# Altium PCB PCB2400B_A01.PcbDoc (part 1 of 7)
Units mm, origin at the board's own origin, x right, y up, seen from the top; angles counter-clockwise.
Board outline 115 x 60 mm, 6 copper layers (Top Layer, Signal Layer 2, Signal Layer 3, Signal Layer 4, Signal Layer 5, Bottom Layer), stack 1.555 mm thick; 382 components, 308 nets, 1384 pads, 1152 vias.
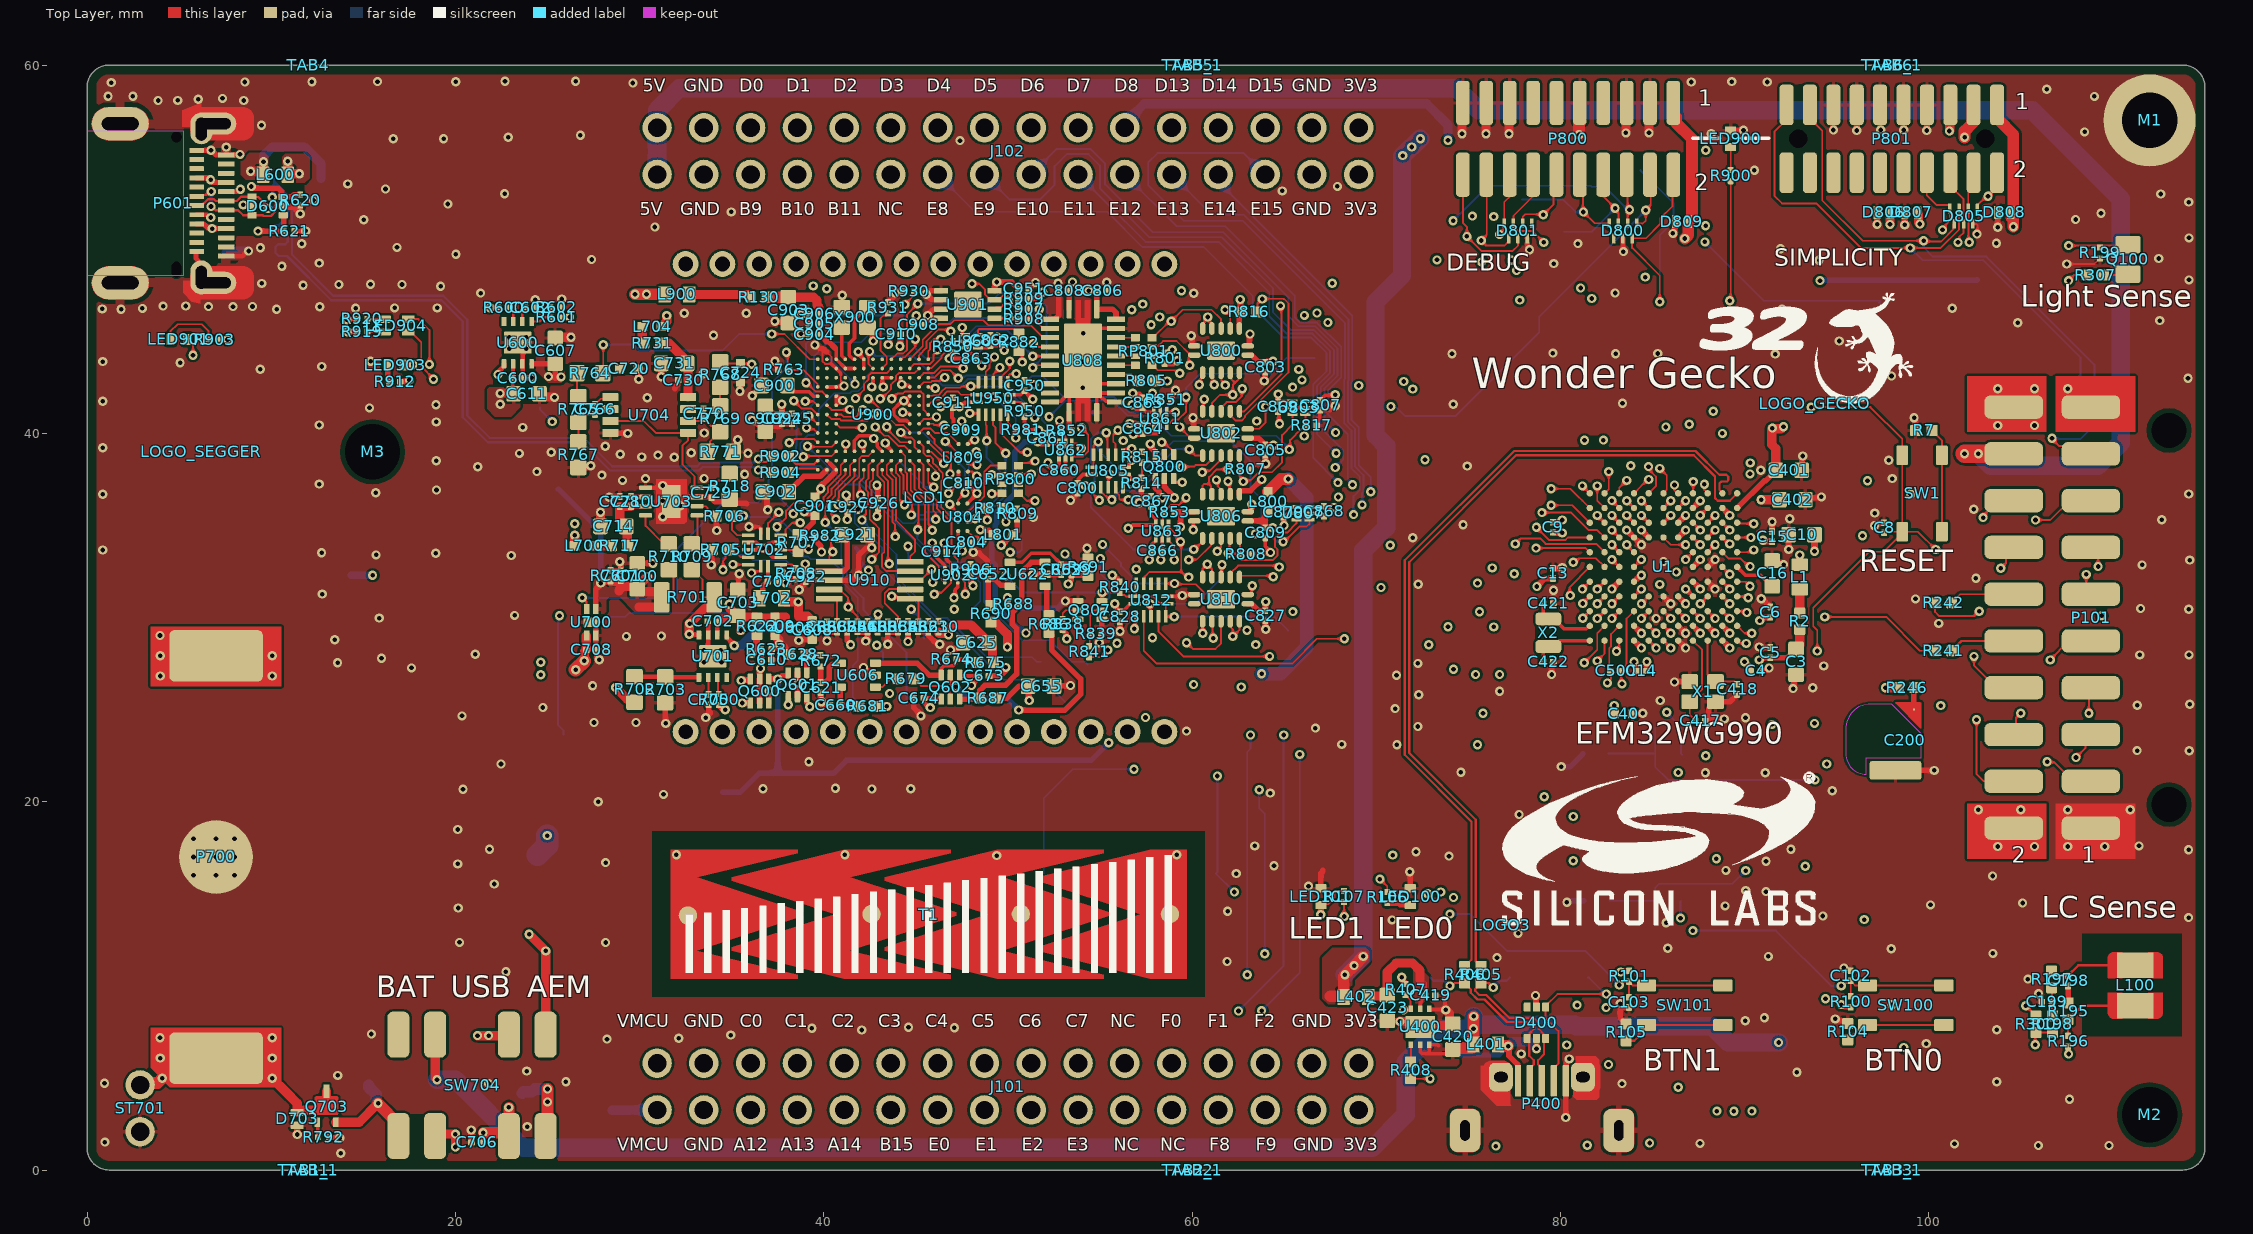
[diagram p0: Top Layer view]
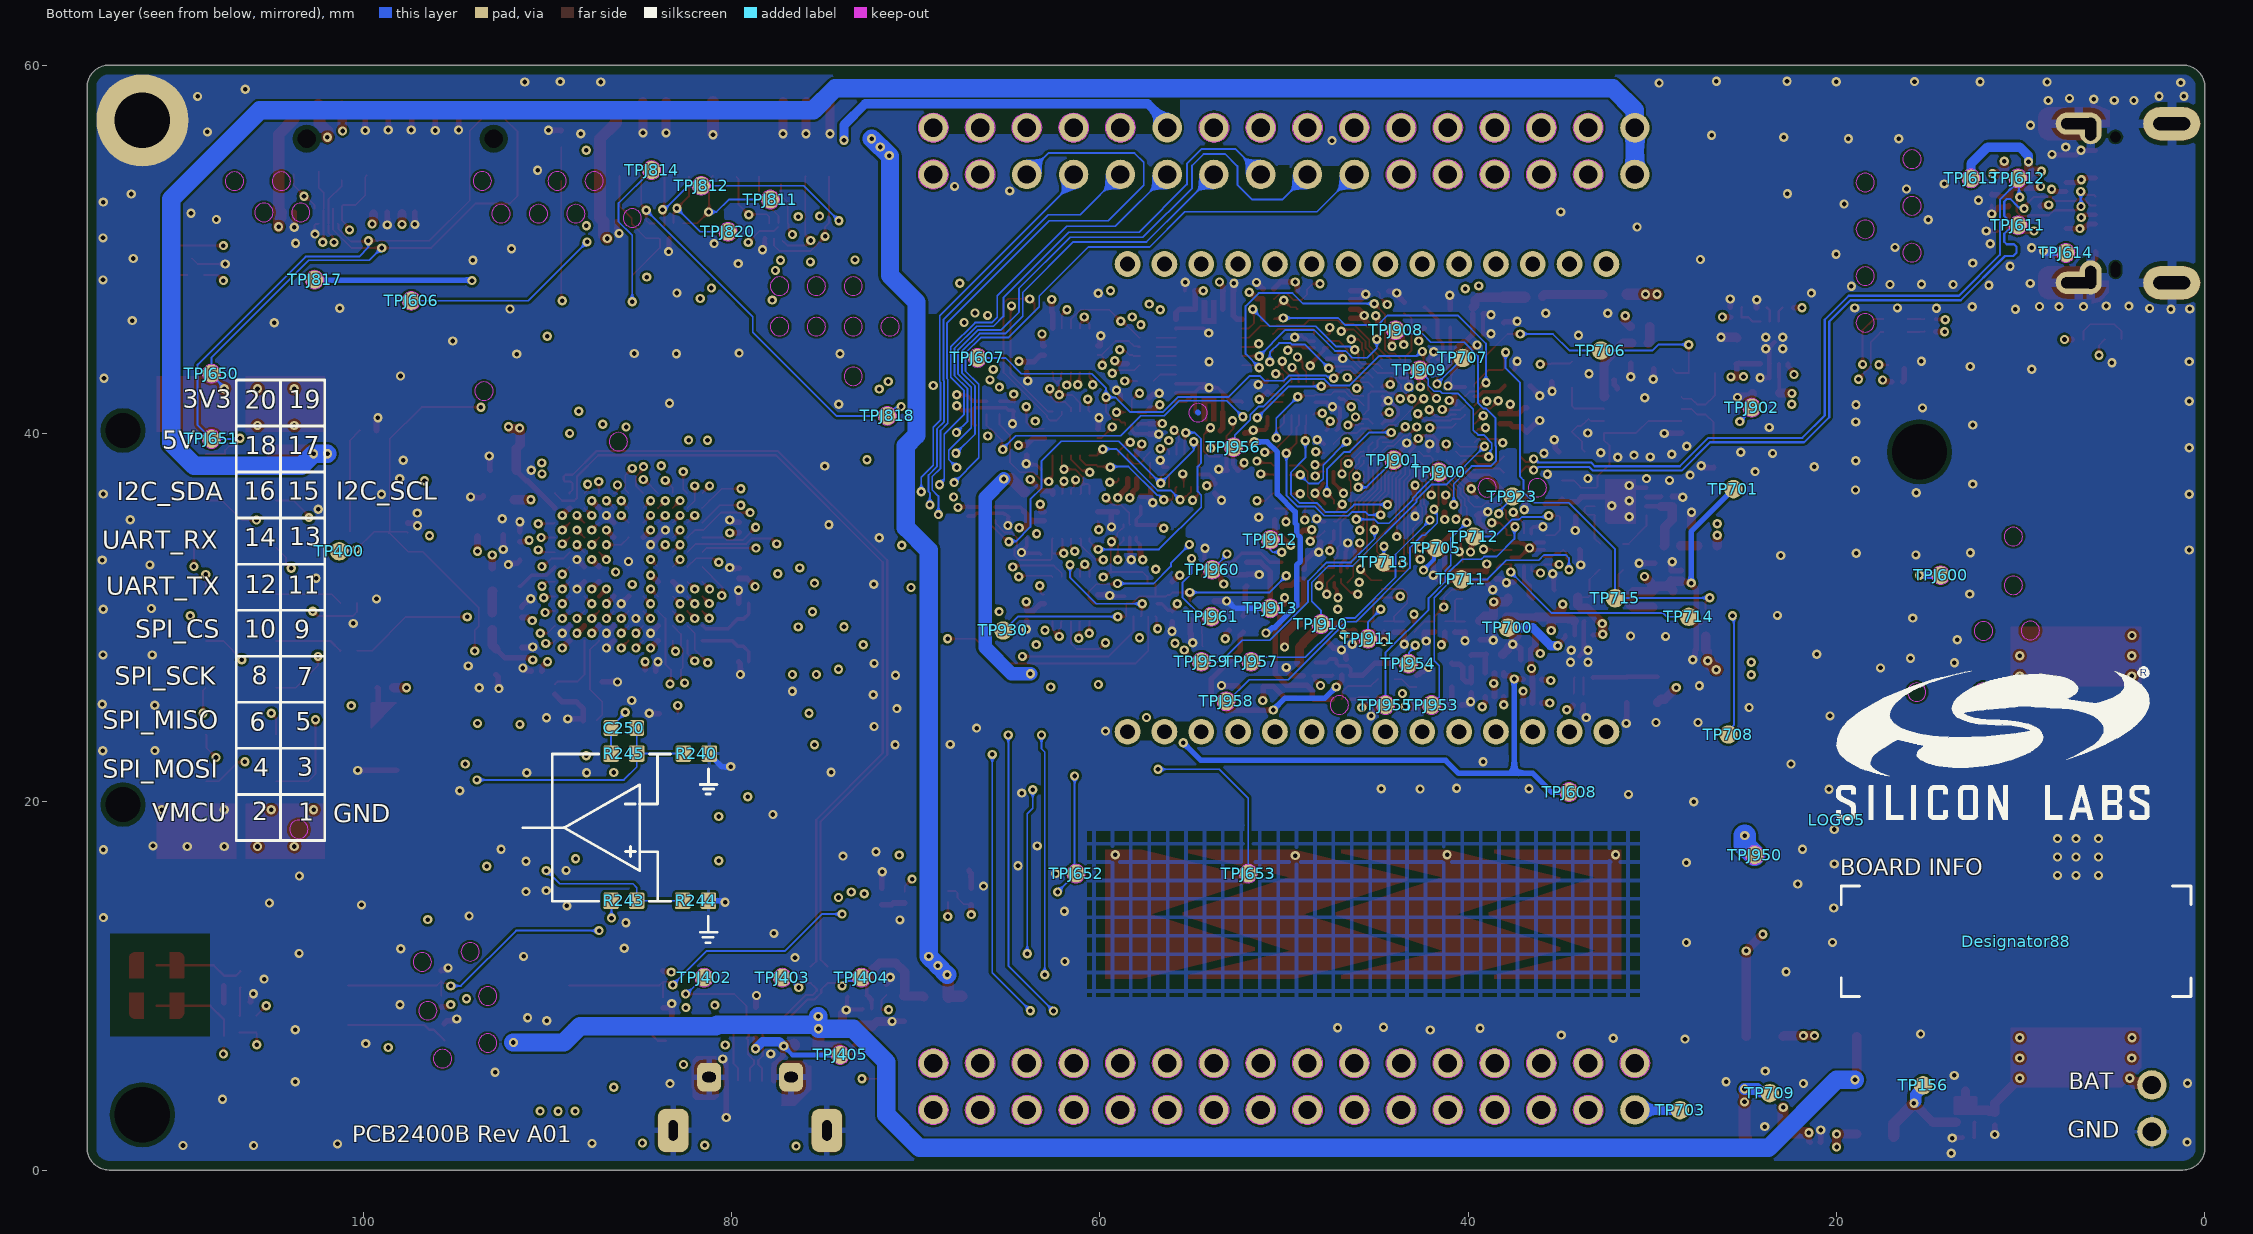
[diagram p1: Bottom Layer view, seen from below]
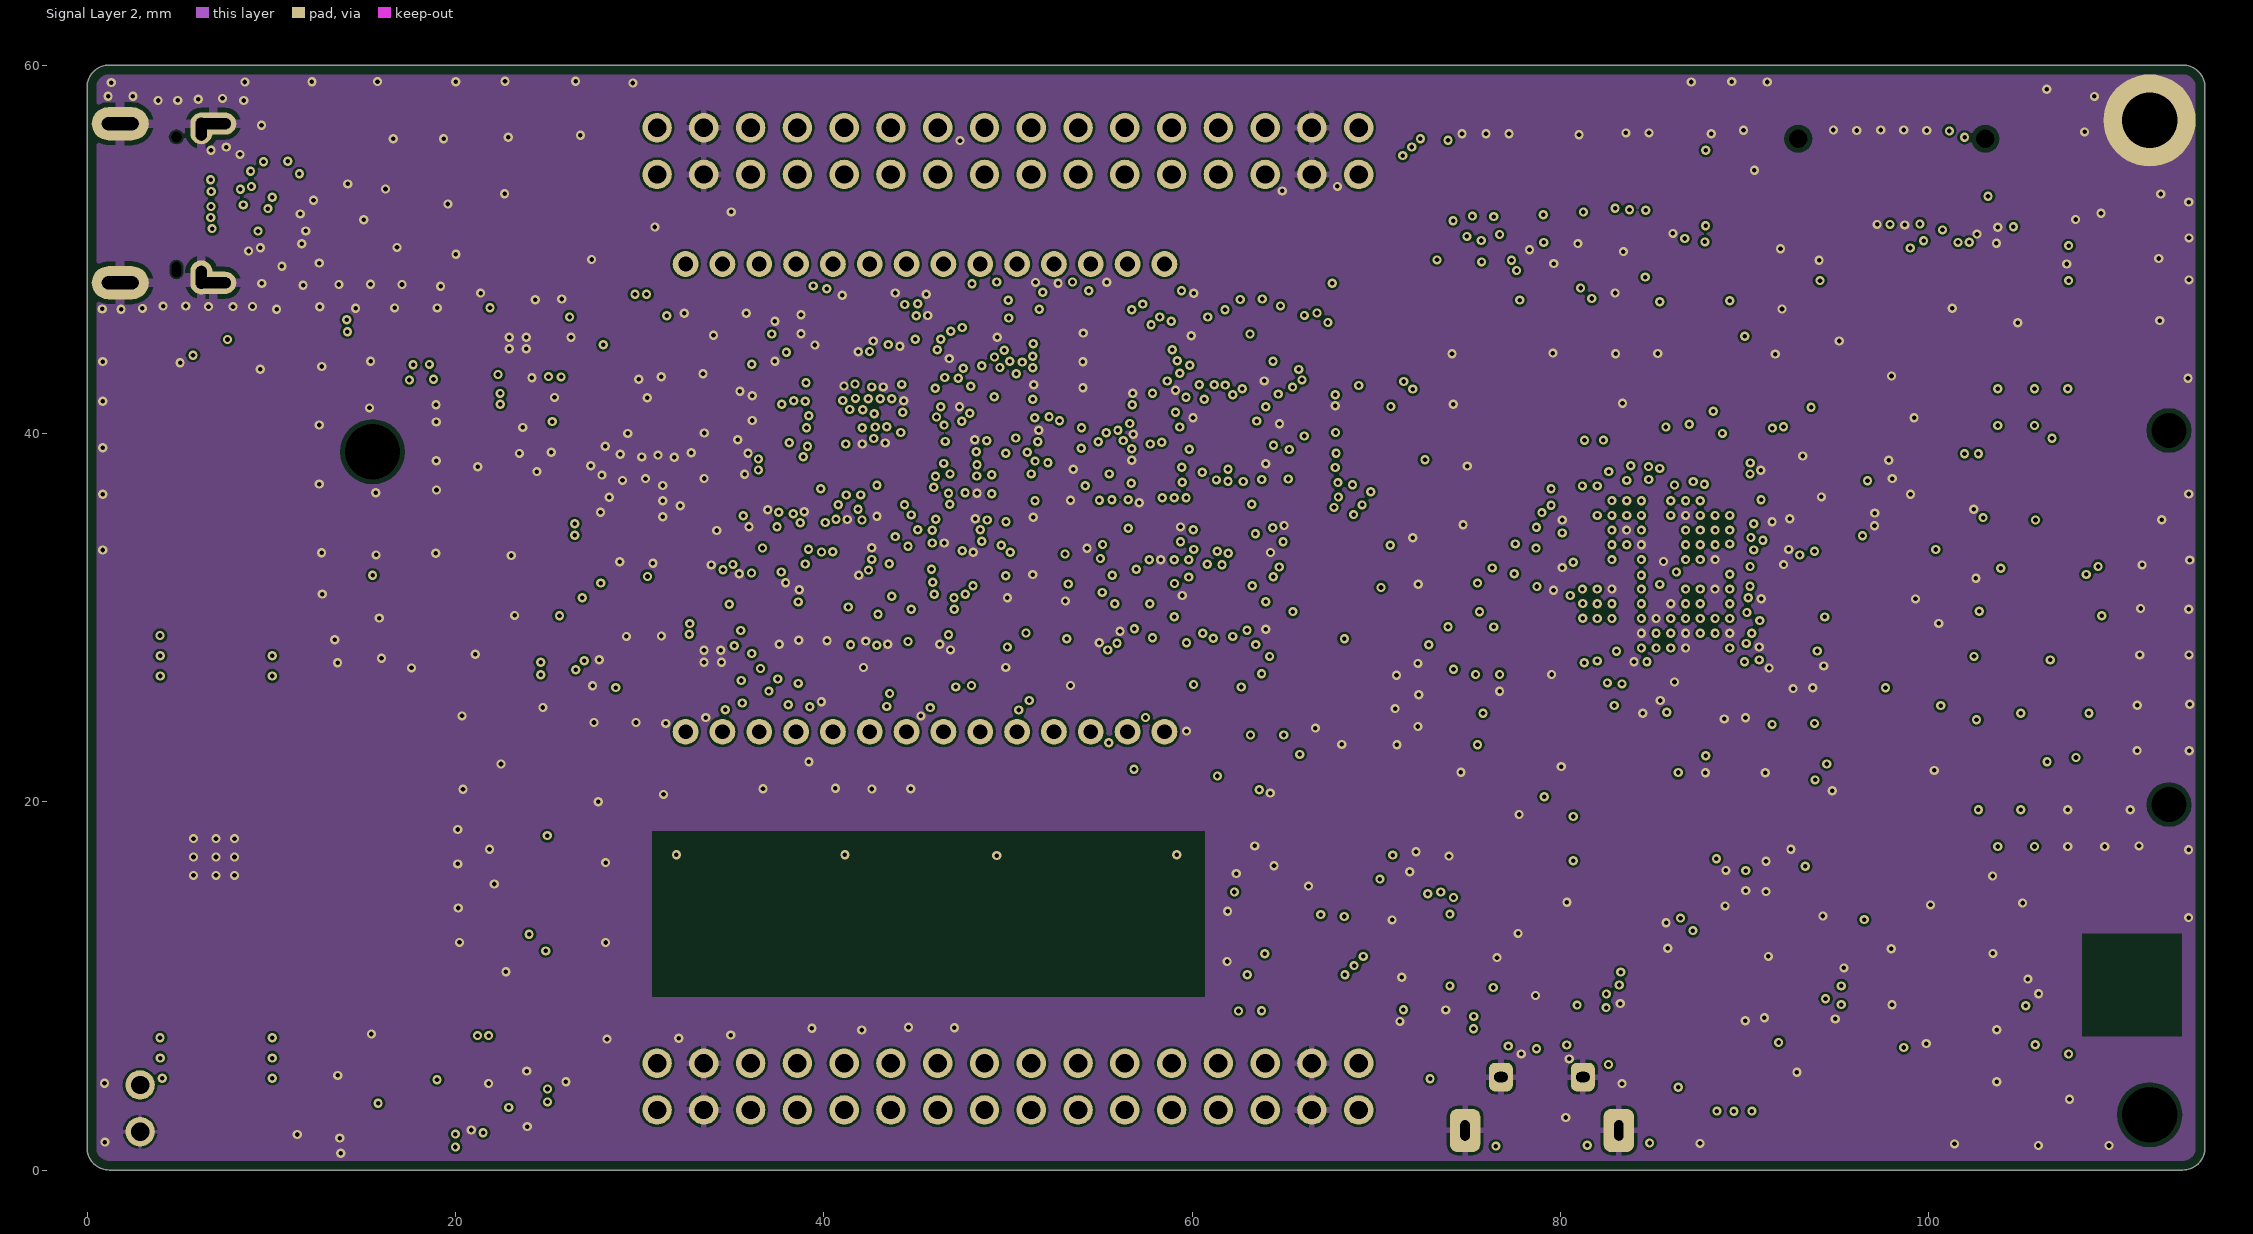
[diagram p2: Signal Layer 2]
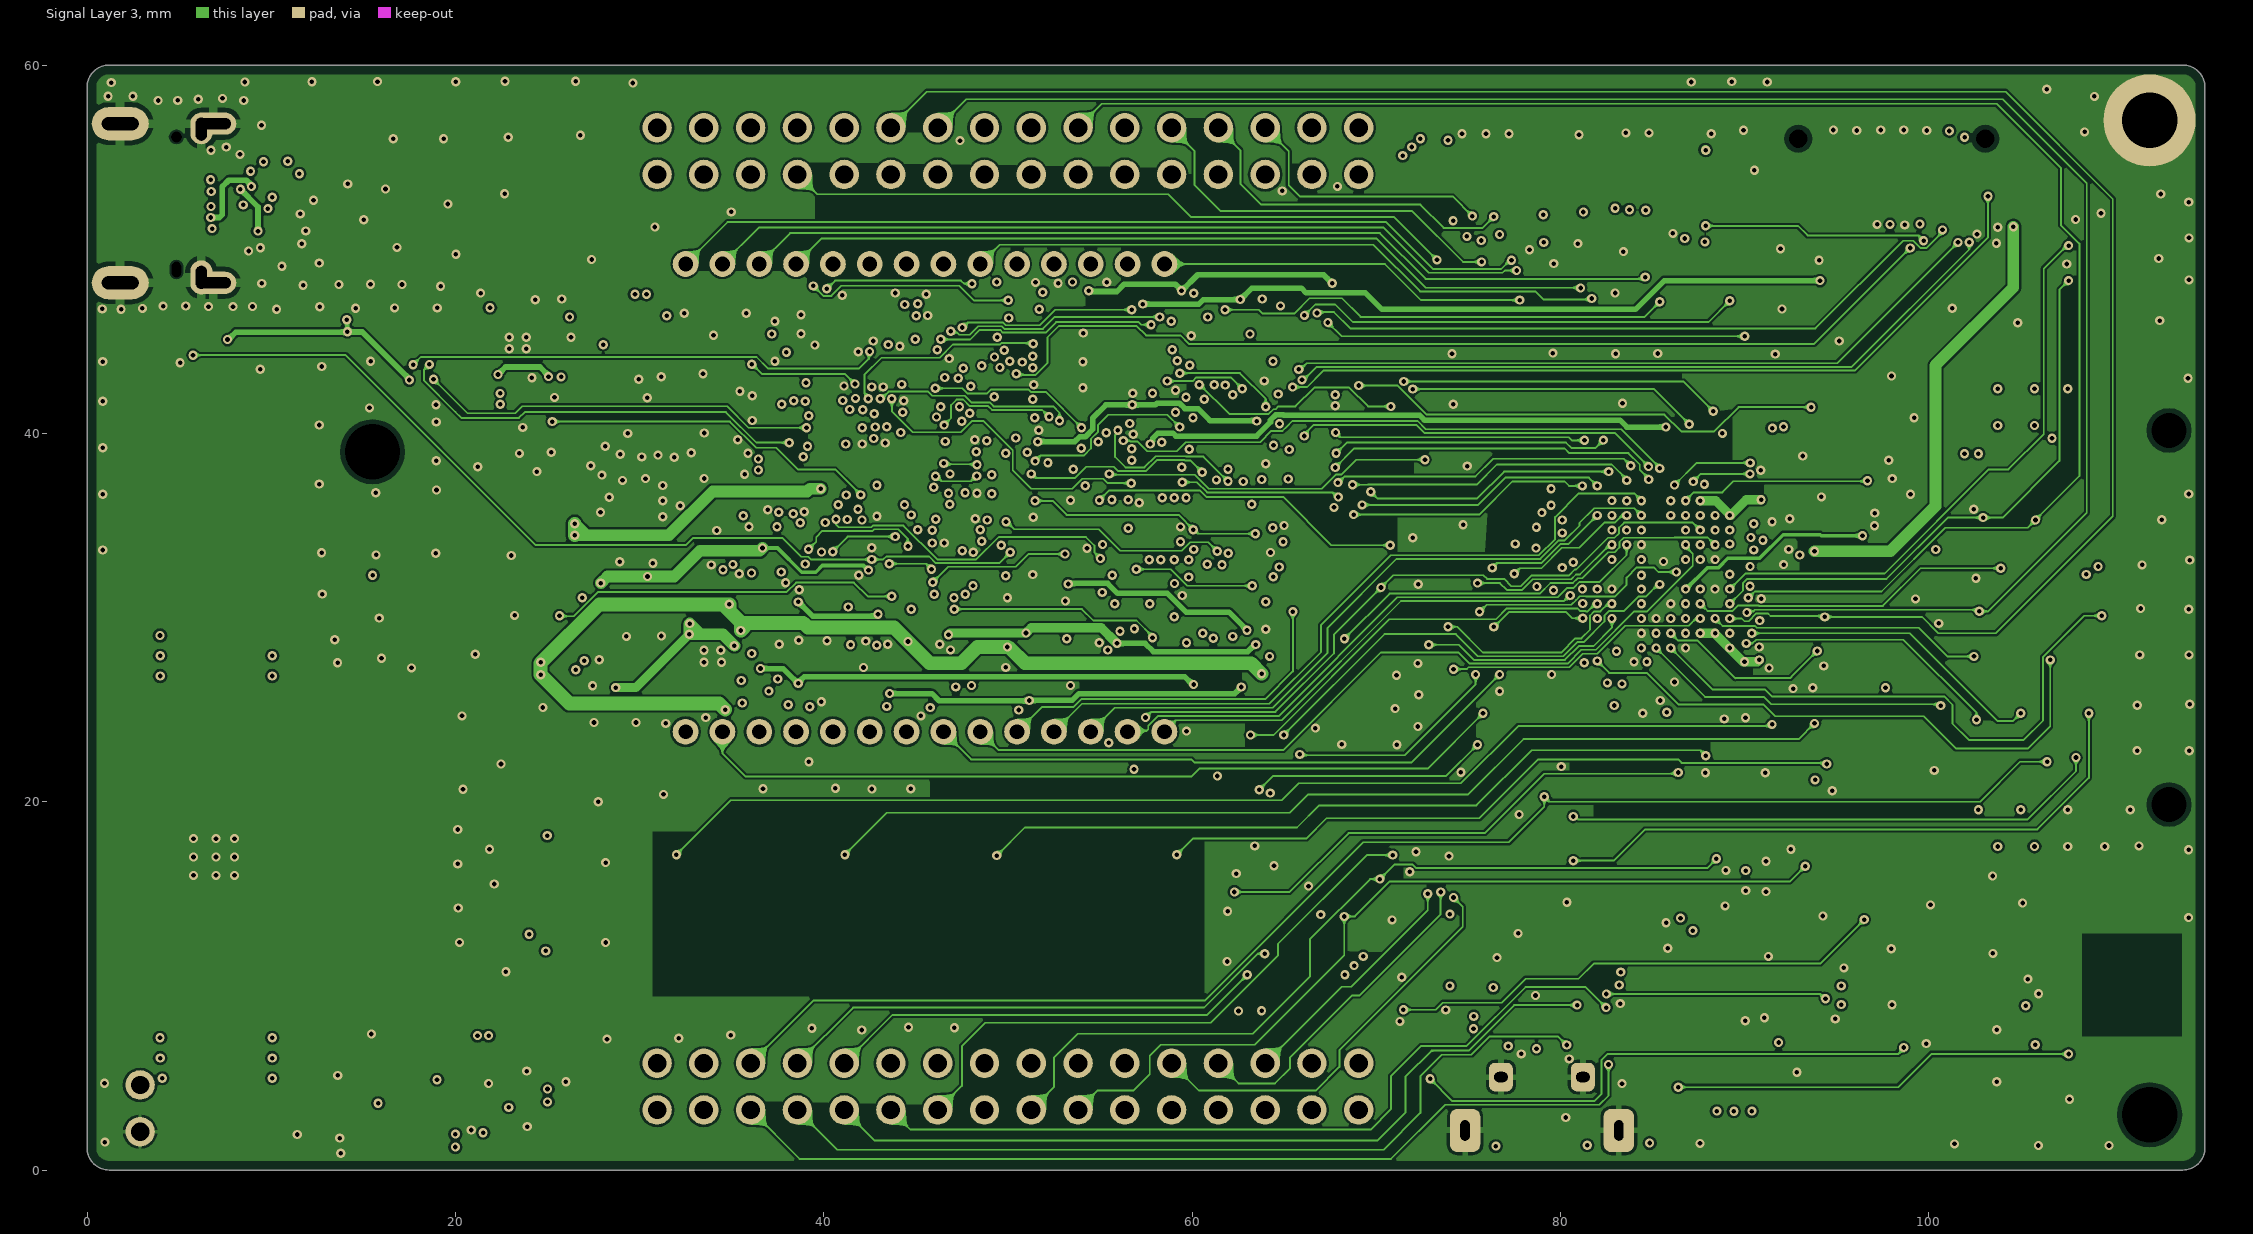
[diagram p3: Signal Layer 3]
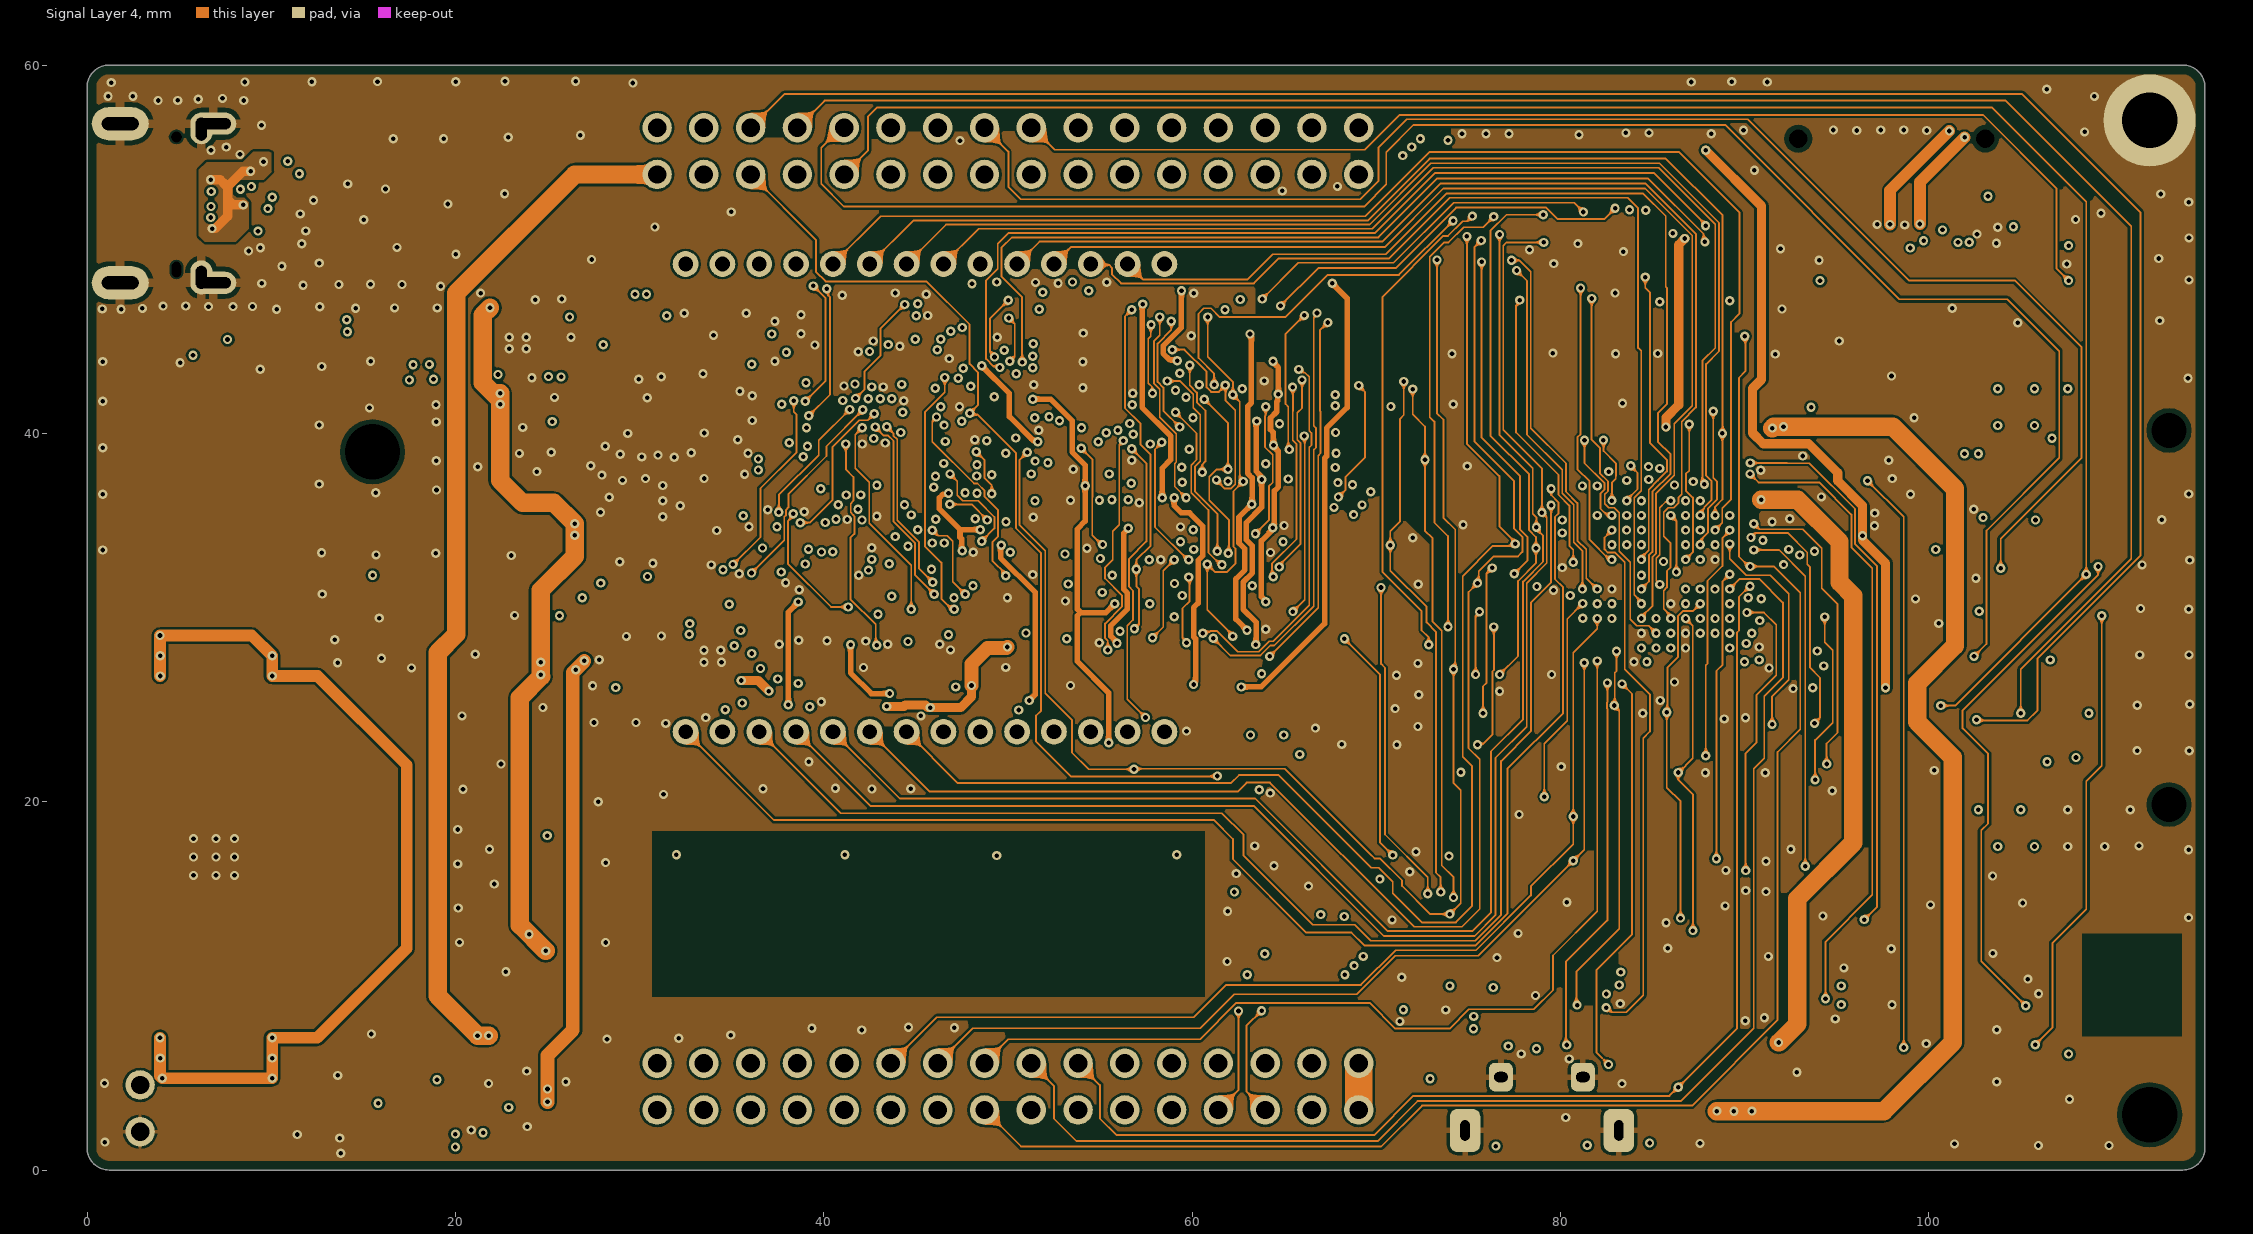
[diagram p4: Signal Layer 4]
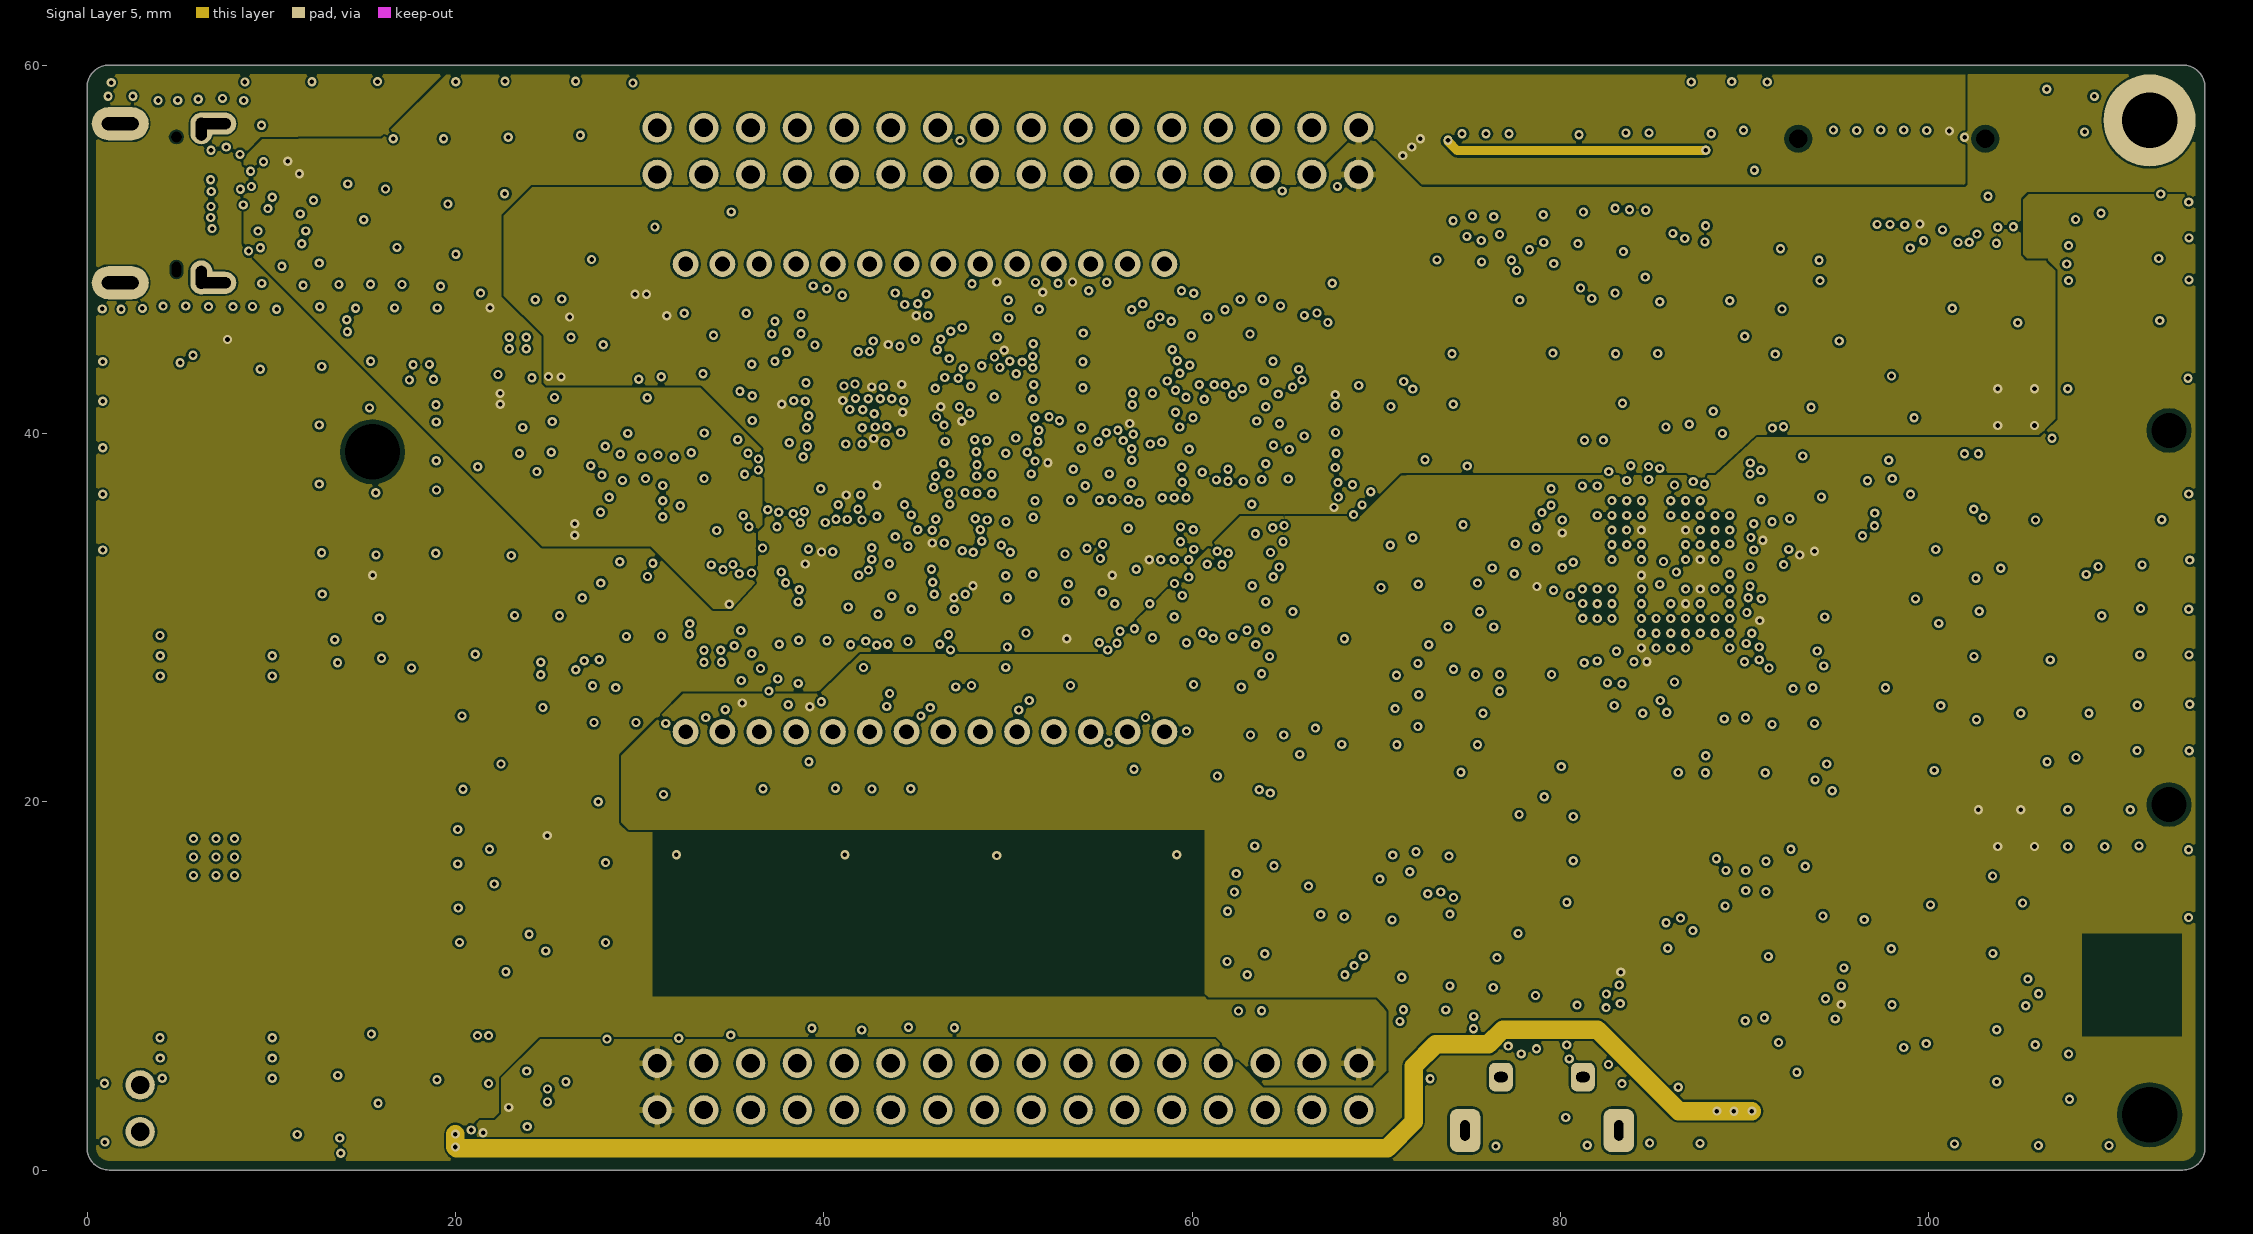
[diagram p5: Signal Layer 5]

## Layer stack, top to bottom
Top Solder: solder mask 0.05, Solder Resist, Dk 3.5
Top Layer: signal copper 0.035
Dielectric 1: prepreg 0.1, FR-4, Dk 4.2
Signal Layer 2: signal copper 0.035
Dielectric 2: core 0.46, FR-4, Dk 4.2
Signal Layer 3: signal copper 0.035
Dielectric 3: prepreg 0.225, FR-4, Dk 4.2
Signal Layer 4: signal copper 0.035
Dielectric 4: core 0.46, FR-4, Dk 4.2
Signal Layer 5: signal copper 0.035
Dielectric 5: prepreg 0.1, FR-4, Dk 4.2
Bottom Layer: signal copper 0.035
Bottom Solder: solder mask 0.05, Solder Resist, Dk 3.5

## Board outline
1.2,0 cw(c1.2,1.2) 0,1.2 0,58.8 cw(c1.2,58.8) 1.2,60 113.8,60 cw(c113.8,58.8) 115,58.8 115,1.2 cw(c113.8,1.2) 113.8,0

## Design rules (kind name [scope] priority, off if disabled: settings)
BoardOutlineClearance BoardOutlineClearance_Ignore_USB [HasFootprint('FCI_10137065_USB-C_RCPT_A1') or IsKeepOut] p1: gap=0.5 ignorepadtopadclearanceinfootprint=FALSE except(0: THPad-OutlineEdge Region-OutlineEdge Region-CavityEdge Region-CutoutEdge Region-SplitBarrior Region-SplitContinuation; 0.26: Arc-CutoutEdge Track-CutoutEdge SMDPad-CutoutEdge THPad-CutoutEdge Via-CutoutEdge Fill-CutoutEdge Poly-CutoutEdge Text-CutoutEdge)
BoardOutlineClearance [Not InPadClass('Outside_Board')] p2: gap=0.5 ignorepadtopadclearanceinfootprint=FALSE except(0.26: Arc-CutoutEdge Track-CutoutEdge SMDPad-CutoutEdge THPad-CutoutEdge Via-CutoutEdge Fill-CutoutEdge Poly-CutoutEdge Region-CutoutEdge Text-CutoutEdge; 0.4: THPad-OutlineEdge Region-OutlineEdge Region-CavityEdge Region-SplitBarrior Region-SplitContinuation)
Clearance Clearance_P601 [InComponent('P601')] p1: gap=0.1 ignorepadtopadclearanceinfootprint=FALSE except(0: Region-Region)
Clearance Clearance_NPL [(ObjectKind = 'Pad') And (Layer = 'MultiLayer') And (PadIsPlated = 'False')] p2: gap=0.25 ignorepadtopadclearanceinfootprint=FALSE
Clearance USB [InNetClass('USB')] p3: gap=0.144 ignorepadtopadclearanceinfootprint=FALSE
Clearance "Clearance_ThermalPad to Via" [IsPad and InNet('GND') vs IsVia] p4 off: gap=-1 ignorepadtopadclearanceinfootprint=FALSE except(0: Arc-Hole Track-Hole SMDPad-Hole THPad-Hole Via-Hole Fill-Hole Poly-Hole Region-Hole Text-Hole)
Clearance Clearance_Polygon_USB [InPolygon vs InNetClass('USB')] p5: gap=0.25 ignorepadtopadclearanceinfootprint=FALSE except(0: Arc-Hole Track-Hole SMDPad-Hole THPad-Hole Via-Hole Fill-Hole Poly-Hole Region-Hole Text-Hole)
Clearance Clearance_Polygon [InPolygon] p6: gap=0.125 ignorepadtopadclearanceinfootprint=FALSE
Clearance Clearance_Via_Track [IsVia vs IsTrack] p7: gap=0.089 ignorepadtopadclearanceinfootprint=FALSE except(0: Arc-Hole Track-Hole SMDPad-Hole THPad-Hole Via-Hole Fill-Hole Poly-Hole Region-Hole Text-Hole)
Clearance Clearance_Via_Pad [IsVia vs IsPad] p8 off: gap=0.025 ignorepadtopadclearanceinfootprint=FALSE except(0: Arc-Hole Track-Hole SMDPad-Hole THPad-Hole Via-Hole Fill-Hole Poly-Hole Region-Hole Text-Hole)
Clearance USB_LINE [InNet('DBGMCU_USB_DM') vs InNet('DBGMCU_USB_DP')] p9: gap=0.102 ignorepadtopadclearanceinfootprint=FALSE
Clearance Pad2PAD [IsPad vs IsPad] p10: gap=0.1 ignorepadtopadclearanceinfootprint=TRUE except(0: Arc-Hole Track-Hole SMDPad-Hole THPad-Hole Via-Hole Fill-Hole Poly-Hole Region-Hole Text-Hole)
Clearance [All] p11: gap=0.1 ignorepadtopadclearanceinfootprint=FALSE
ComponentClearance [All] p1: gap=0.1 collisioncheckmode=3 verticalgap=0.254 showdistances=TRUE
DiffPairsRouting [InAnyDifferentialPair] p1: maxlimit=0.12 minlimit=0.12 mostfreqgap=0.12 toplayer_minwidth=0.12 toplayer_maxwidth=0.12 toplayer_prefwidth=0.12 midlayer1_minwidth=0.12 midlayer1_maxwidth=0.12 midlayer1_prefwidth=0.12 midlayer2_minwidth=0.12 midlayer2_maxwidth=0.12 midlayer2_prefwidth=0.12 midlayer3_minwidth=0.12 midlayer3_maxwidth=0.12 midlayer3_prefwidth=0.12 midlayer5_minwidth=0.12 midlayer5_maxwidth=0.12 midlayer5_prefwidth=0.12 bottomlayer_minwidth=0.12 bottomlayer_maxwidth=0.12 bottomlayer_prefwidth=0.12 maxuncoupledlength=12.7
HoleSize [All] p1: absolutevalues=TRUE maxlimit=10 minlimit=0.1 maxpercent=80.000 minpercent=20.000
HoleToHoleClearance [InComponent('P601') vs InComponent('P601')] p1: gap=0 allowstackedmicrovias=TRUE
HoleToHoleClearance HoleToHoleClearance_U1toVIA_1 [InComponent ('U1') vs IsVia] p2: gap=0 allowstackedmicrovias=TRUE
HoleToHoleClearance HoleToHoleClearance_general [All] p3: gap=0.254 allowstackedmicrovias=TRUE
MinimumSolderMaskSliver [All] p1: minsoldermaskwidth=0.102
ParallelSegment [InNet('MCU_PC11') OR InNet('MCU_PC10') OR InNet('MCU_PC9') OR InNet('MCU_PC8')] p1: limit=12 gap=0.49
PolygonConnect [InComponent('J101') or InComponent('J102') vs InNet('GND')and not OnLayer('Signal Layer 2')] p1: connectstyle=NoConnect reliefconductorwidth=0.254 reliefentries=4 polygonreliefangle="90 Angle" airgapwidth=0.125
PolygonConnect PolygonConnect_TH [InComponent('J101') Or InComponent('J102') Or InComponent('ST1') Or InComponent('P400') Or InComponent('J710')] p2: connectstyle=Relief reliefconductorwidth=0.33 reliefentries=4 polygonreliefangle="90 Angle" airgapwidth=0.152
PolygonConnect PolygonConnect_P601 [InComponent('P601')] p3: connectstyle=Relief reliefconductorwidth=0.508 reliefentries=4 polygonreliefangle="90 Angle" airgapwidth=0.254
PolygonConnect PolygonConnect_M1 [InComponent('M1')] p4: connectstyle=Direct reliefconductorwidth=0.33 reliefentries=4 polygonreliefangle="90 Angle" airgapwidth=0.152
PolygonConnect PolygonConnect_P700 [InComponent('P700')] p5: connectstyle=Direct reliefconductorwidth=0.33 reliefentries=4 polygonreliefangle="90 Angle" airgapwidth=0.152
PolygonConnect Polygon_VIA_Connect [IsVia] p6: connectstyle=Direct reliefconductorwidth=0.254 reliefentries=4 polygonreliefangle="90 Angle" airgapwidth=0.254
PolygonConnect PolygonConnect_general [All] p7: connectstyle=Relief reliefconductorwidth=0.2 reliefentries=4 polygonreliefangle="90 Angle" airgapwidth=0.127
RoutingVias [All] p1: holewidth=0.25 width=0.5 viastyle="Through Hole" minholewidth=0.25 minwidth=0.5 maxholewidth=1 maxwidth=1.5
ShortCircuit ShortCircuit_General [All] p1: allowed=FALSE
SilkToSilkClearance [All] p1: silktosilkclearance=0.102
SilkToSolderMaskClearance [IsPad] p1: minsilkscreentomaskgap=0.102 clearancetoexposedcopper=TRUE
SolderMaskExpansion [All] p1: expansion=0.051 istentingtop=FALSE
UnRoutedNet [All] p1: checkbadconnections=TRUE
UnpouredPolygon [All] p1: allowunpoured=TRUE allowshelved=TRUE
Width Width_1 [InNetClass('USB')] p1: maxlimit=0.106 minlimit=0.106 preferedwidth=0.106
Width [All] p2: maxlimit=5.08 minlimit=0.1 preferedwidth=0.102
20 further rules are at their usual default settings.

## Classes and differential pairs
differential pair class USB: USB1 usb2 usb3
pad class Outside_Board: P400-8 P400-9 P400-10 P400-11
differential pair usb3: +N17457251 -N17457255
differential pair usb2: +EFM_USB_DP -EFM_USB_DM
differential pair USB1: +USB_DP -USB_DM

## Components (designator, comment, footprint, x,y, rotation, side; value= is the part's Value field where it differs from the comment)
C3 "10U" C0603 92.8,27.6 r270 top
C4 "10N" C0201 90.6,27.1 r0 top
C5 "10N" C0201 91.4,28.1 r90 top
C6 "100N" C0201 91.4,30.3 r90 top
C8 "100N" C0201 97.581,34.881 r90 top
C9 "100N" C0201 79.6,34.9 r90 top
C10 "10U" C0603 93.1,34.5 r180 top
C13 "100N" C0201 79.6,32.4 r90 top
C14 "100N" C0201 84.4,27.1 r180 top
C15 "100N" C0201 91.5,34.4 r90 top
C16 "1U" C0603 91.5,32.4 r90 top
C40 "1U" C0402 83.425,24.767 r0 top
C102 "1N" C0201 95.769,10.548 r90 top
C103 "1N" C0201 83.727,9.099 r270 top
C198 "330P" C0201 107.568,10.269 r270 top
C199 "100N" C0201 106.425,9.126 r180 top
C200 "33 mF" BAT_SEIKO_XH311HG 97.5,23.3 r90 top
C250 "100N" C0603 85.851,24.003 r0 bottom
C401 "1U" C0603 92.4,38 r0 top
C402 "4U7" C0603 92.6,36.4 r0 top
C417 "15P" C0201 87.6,24.4 r0 top
C418 "15P" C0201 89.6,26.1 r270 top
C419 "100N" C0201 72.934,9.485 r0 top
C420 "1U" C0603 74.151,7.245 r90 top
C421 "18P" C0201 79.35,30.775 r0 top
C422 "18P" C0201 79.35,27.6 r0 top
C423 "10U" C0603 70.605,8.802 r270 top
C500 "22N" C0201 83,27.1 r180 top
C600 "100N" C0201 23.387,43.005 r0 top
C602 "33N" C0201 24.062,46.83 r0 top
C607 "10U" C0603 25.412,44.48 r90 top
C608 "1U" C0402 39.375,29.325 r270 top
C609 "1U" C0402 37.35,29.525 r270 top
C610 "1N" C0201 36.882,27.702 r0 top
C611 "10U" C0603 23.862,42.155 r0 top
C621 "100N" C0201 39.825,26.2 r270 top
C625 "10U" C0603 48.276,28.638 r180 top
C632 "10N" C0201 45.125,29.5 r270 top
C635 "10N" C0201 43.475,29.5 r270 top
C638 "10N" C0201 40.175,29.5 r270 top
C641 "10N" C0201 41.825,29.5 r270 top
C652 "100N" C0201 48.925,32.35 r90 top
C653 "100N" C0201 52.9,32.6 r270 top
C655 "10U" C0603 51.8,26.275 r0 top
C660 "100N" C0201 40.625,25.25 r180 top
C673 "100N" C0201 48.699,26.829 r0 top
C674 "100N" C0201 45.171,25.632 r180 top
C700 "10U" C0603 29.875,32.25 r90 top
C701 "100N" C0201 28.975,32.275 r90 top
C702 "100N" C0201 33.975,29.8 r180 top
C703 "10U" C0603 35.325,30.8 r90 top
C705 "33N" C0201 33.75,25.55 r270 top
C706 "100N" C0201 21.15,1.5 r180 top
C707 "100N" C0201 37.225,31.95 r0 top
C708 "100N" C0201 27.375,28.25 r0 top
C710 "100N" C0201 29.525,36.3 r90 top
C714 "10U" C0603 28.575,34.95 r180 top
C720 "1N" C0402 29.425,43.5 r0 top
C724 "1N" C0402 35.475,43.3 r270 top
C728 "100N" C0201 28.925,36.3 r90 top
C729 "2N2" C0201 33.9,36.775 r270 top
C730 "100N" C0201 32.375,42.9 r180 top
C731 "10U" C0603 31.875,43.8 r180 top
C766 "10P" C0201 27.575,41.3 r90 top
C770 "10P" C0201 33.475,41.075 r90 top
C800 "100N" C0201 53.775,37.025 r270 top
C803 "100N" C0201 63.975,43.6 r270 top
C804 "100N" C0201 47.745,34.083 r0 top
C805 "100N" C0201 63.975,39.1 r270 top
C806 "100N" C0201 55.125,47.75 r0 top
C807 "100N" C0201 66.95,41.525 r270 top
C808 "100N" C0201 53.025,47.75 r180 top
C809 "100N" C0201 63.975,34.6 r270 top
C810 "100N" C0201 47.575,37.3 r0 top
C827 "100N" C0201 63.975,30.1 r270 top
C828 "100N" C0201 56.075,30.05 r270 top
C860 "100N" C0201 52.8,38 r0 top
C861 "100N" C0201 52.125,39.725 r90 top
C862 "100N" C0201 49.05,45.05 r90 top
C863 "100N" C0201 47.97,44.064 r180 top
C864 "100N" C0201 57.325,40.25 r270 top
C865 "100N" C0201 57.312,41.67 r90 top
C866 "100N" C0201 58.1,33.625 r0 top
C867 "100N" C0201 57.78,36.306 r90 top
C868 "100N" C0201 67.162,35.77 r270 top
C869 "100N" C0201 64.663,41.445 r270 top
C870 "100N" C0201 64.964,35.72 r270 top
C900 "1U" C0603 37.325,42.6 r180 top
C901 "1U" C0402 39.525,36.05 r270 top
C902 "4U7" C0603 37.4,36.825 r180 top
C903 "10U" C0603 38.075,46.7 r270 top
C904 "10N" C0201 39.474,45.369 r180 top
C905 "10N" C0201 39.474,45.945 r180 top
C906 "10N" C0201 39.474,46.494 r180 top
C907 "4U7" C0603 36.825,40.8 r270 top
C908 "100N" C0201 45.144,45.9 r0 top
C909 "100N" C0201 47.43,40.176 r180 top
C910 "100N" C0201 43.902,45.378 r0 top
C911 "100N" C0201 47.011,41.66 r270 top
C914 "100N" C0201 46.403,33.565 r0 top
C921 "4U7" C0603 41.675,34.5 r0 top
C922 "100N" C0201 39.025,32.225 r270 top
C924 "100N" C0201 37.725,40.8 r270 top
C925 "100N" C0201 38.275,40.8 r270 top
C926 "100N" C0201 42.95,36.2 r270 top
C927 "100N" C0201 41.3,36 r270 top
C950 "10N" C0201 50.9,42.6 r90 top
C951 "100N" C0201 50.85,47.85 r0 top
D400 "DT1446-04" SOT563_DIODES 78.7,8 r270 top
D600 "DT1446-04" SOT563_DIODES 9.8,52.35 r180 top
D703 "ESD" X2-DFN1006-2 11.403,2.773 r270 top
D800 "PUSB3AB6" DFN2111-7_M050_1.2X2.1_NXP 83.4,51 r270 top
D801 "PUSB3AB6" DFN2111-7_M050_1.2X2.1_NXP 77.7,51 r270 top
D805 "PUSB3AB6" DFN2111-7_M050_1.2X2.1_NXP 101.9,51.8 r270 top
D806 "ESD" X2-DFN1006-2 97.55,52 r180 top
D807 "ESD" X2-DFN1006-2 99.05,52 r180 top
D808 "ESD" X2-DFN1006-2 104.1,52 r180 top
D809 "ESD" X2-DFN1006-2 86.6,51.5 r180 top
Designator88 "Comment" LABEL_4CORNERS_19.0X6.0 10.25,12.425 r180 bottom
J101 "HEADER_2X16_2.54MM_TH" HDR_M254_RING-2X16 50,4.532 r0 top
J102 "HEADER_2X16_2.54MM_TH" HDR_M254_RING-2X16 50,55.332 r0 top
L1 "74279266" COIL_WURTH_CBF_0603 93,32.2 r270 top
L100 "390uH" COIL_BOURNS_SDR0302 111.222,10.025 r270 top
L401 "742792662" COIL_WURTH_CBF_0603 75.951,6.821 r180 top
L402 "742792662" COIL_WURTH_CBF_0603 68.9,9.4 r0 top
L600 "742792662" COIL_WURTH_CBF_0603 10.225,54.05 r0 top
L700 "742792796" COIL_0402 27,33.9 r0 top
L702 "74279266" COIL_WURTH_CBF_0603 37.175,31.05 r180 top
L704 "742792796" COIL_0402 30.675,45.8 r180 top
L800 "742792796" COIL_0402 64.125,36.3 r270 top
L801 "742792796" COIL_0402 49.75,34.5 r180 top
L900 "74279266" COIL_WURTH_CBF_0603 32.025,47.55 r0 top
LCD1 "CL010-1087-04" LCD_TRI-T_CL010-1087-03 45.5,36.5 r0 top
LED100 "YELLOW" LED_0402_CAT2 71.85,14.846 r90 top
LED101 "YELLOW" LED_0402_CAT2 67,14.846 r90 top
LED900 "Yellow" LED_0402_CAT2 89.25,56 r90 top
LED901 "Blue" LED_0402_CAT2 4.98,45.11 r0 top
LED903 "RED" LED_0402 16.739,43.71 r180 top
LED904 "LED_G_R" LED_AVAGO_HSMF-C165-4 16.789,45.86 r0 top
LOGO3 "Comment" LOGO_SILABS_W18.0 76.85,13.3 r0 top
LOGO5 "Comment" LOGO_SILABS_W18.0 20,19 r180 bottom
LOGO_GECKO "Comment" LOGO_GECKO_H6.0 93.816,41.616 r0 top
LOGO_SEGGER "Comment" LOGO_SEGGER_10.0X5.0_SM 6.2,39 r0 top
M1 "HOLE_PTH_3MM" HOLE_3.0_5.0_PL 112,57 r0 top
M2 "HOLE_TH_3MM" HOLE_3.0_NPL 112,3 r0 top locked
M3 "Comment" HOLE_3.0_NPL 15.5,39 r0 top
P101 "HEADER_2X10_2.54MM_TH" WCON_1125B-1210_HOR_PEG-2X10 113.053,19.84 r90 top
P400 "USB_Micro_AB" KLS_KLS1-5245 79,0 r0 top
P601 "AMPH_10137065" FCI_10137065_USB-C_RCPT_A1 4.85,52.5 r270 top
P700 "CR2032" BAT_HOLD_MPD_BK-912_CR2032 7,17 r90 top
P800 "HEADER_DEBUG_ETM" WCON_3132_HDR_M127_SMD-2X10 80.425,56 r180 top
P801 "HEADER_2X10_1.27MM_SMD" HDR_SULLINS_M127_PEG-2X10 103.08,56 r180 top
Q100 "TEMT6200FX01" TEMT6200FX01_GEN_0805 110.825,49.45 r90 top
Q600 "BSS84" SOT563 36.513,26.01 r90 top
Q601 "DMN5L06VK" SOT563 38.575,26.35 r90 top
Q602 "BSS84" SOT563 46.875,26.225 r90 top
Q703 "DMG3415" X2-DFN2015-3_DIODES 13,3.5 r90 top
Q800 "DMN5L06VK" SOT563 58.5,38.2 r270 top
Q807 "DMN5L06VK" SOT563 54.45,30.4 r180 top
R2 "1R" R0402 93,29.8 r270 top
R7 "100R" R0402 99.737,40.162 r0 top
R100 "1M" R0201 95.769,9.135 r270 top
R101 "1M" R0201 83.736,10.521 r90 top
R104 "100R" R0402 95.607,7.506 r90 top
R105 "100R" R0402 83.574,7.47 r90 top
R106 "2K05" R0201 70.6,14.8 r90 top
R107 "2K05" R0201 68.25,14.85 r270 top
R130 "1R" R0402 36.475,47.4 r0 top
R195 "0R" R0402 107.572,8.625 r90 top
R196 "1K5" R0201 107.568,6.993 r90 top
R197 "0R" R0402 106.677,10.35 r90 top
R198 "0R" R0402 106.722,7.925 r90 top
R199 "22K" R0201 109.3,49.8 r270 top
R240 "10K" R0603 81.918,22.617 r0 bottom
R241 "0R" R0402 100.8,28.2 r0 top
R242 "0R" R0402 100.8,30.8 r0 top
R243 "10K" R0603 85.851,14.625 r0 bottom
R244 "10K" R0603 81.963,14.625 r0 bottom
R245 "10K" R0603 85.851,22.617 r0 bottom
R246 "100R" R0402 98.8,26.2 r0 top
R300 "0R" R0402 105.825,7.925 r90 top
R307 "0R" R0402 109.036,48.6 r0 top
R405 "15R" R0402 75.7,10.6 r90 top
R406 "15R" R0402 74.8,10.6 r90 top
R407 "1M" R0201 71.594,9.803 r270 top
R408 "0R" R0402 71.874,5.418 r90 top
R600 "10K" R0201 22.637,46.83 r180 top
R601 "180K" R0201 25.462,46.305 r0 top
R602 "110K" R0201 25.462,46.855 r180 top
R620 "5K1" R0201 11.575,52.675 r90 top
R621 "5K1" R0201 10.97,50.987 r180 top
R622 "47R" R0402 36.375,29.525 r90 top
R623 "10K" R0201 36.882,28.287 r180 top
R628 "1M" R0402 38.575,28 r180 top
R629 "1K" R0201 53.45,32.6 r270 top
R630 "4K7" R0201 46.225,29.5 r270 top
R631 "10K" R0201 45.675,29.5 r90 top
R633 "47K" R0201 44.575,29.5 r270 top
R634 "47K" R0201 44.025,29.5 r90 top
R636 "47K" R0201 41.275,29.5 r270 top
R637 "47K" R0201 40.725,29.5 r90 top
R639 "47K" R0201 42.925,29.5 r90 top
R640 "47K" R0201 42.375,29.5 r90 top
R672 "1K" R0201 39.825,27.65 r90 top
R674 "4K7" R0201 46.925,27.75 r180 top
R675 "3R3" R0402 48.762,27.549 r0 top
R679 "0R" R0402 44.45,26.675 r0 top
R681 "33R" R0402 42.35,25.175 r0 top
R686 "0R" R0402 52.225,29.65 r270 top
R687 "3R3" R0402 48.9,25.625 r0 top
R688 "4K7" R0201 50.3,30.725 r180 top
R690 "33R" R0402 49.075,30.2 r270 top
R691 "1M" R0402 54.351,32.733 r90 top
R700 "10K" R0201 34.3,25.55 r270 top
R701 "4R7" R1206 32.625,31.1 r180 top
R702 "180K" R0603 29.725,26.096 r270 top
R703 "110K" R0603 31.383,26.073 r90 top
R705 "267R" R0402 34.403,33.685 r0 top
R706 "10K2" R0402 34.603,35.503 r0 top
R707 "24K9" R0402 38.6,34.052 r270 top
R708 "1M" R0201 38.483,32.379 r90 top
R709 "1K8" R0603 32.832,33.3 r270 top
R710 "1K8" R0603 31.59,33.3 r270 top
R717 "10R" R0402 28.925,33.9 r0 top
R718 "12K" R0603 34.893,37.125 r90 top
R731 "1R" R0402 30.675,44.9 r180 top
R760 "330K" R0201 28.425,32.275 r270 top
R763 "100K" R0201 37.825,43.45 r0 top
R764 "90R9" R0603 27.3,43.275 r0 top
R765 "51K" R0603 26.675,41.3 r90 top
R767 "160R" R0603 26.675,38.85 r90 top
R768 "90R9" R0603 34.375,43.2 r90 top
R769 "51K" R0603 34.375,40.8 r90 top
R771 "51K" R0603 34.375,39 r180 top
R792 "1K" R0201 12.834,1.782 r180 top
R801 "47K" R0201 58.514,44.082 r270 top
R805 "33R" R0402 57.525,42.85 r0 top
R807 "100K" R0201 62.9,38.05 r0 top
R808 "100K" R0201 62.919,33.444 r0 top
R809 "100K" R0201 50.5,35.625 r270 top
R810 "33R" R0402 49.275,35.925 r0 top
R814 "100K" R0201 57.254,37.3 r90 top
R815 "1K" R0201 57.276,38.706 r270 top
R816 "100K" R0402 63.075,46.6 r180 top
R817 "100K" R0201 66.47,40.436 r180 top
R838 "100K" R0201 52.975,29.625 r270 top
R839 "10M" R0201 54.775,29.125 r180 top
R840 "100K" R0201 56.075,31.65 r90 top
R841 "1K" R0201 54.411,28.145 r270 top
R850 "100K" R0201 47.007,44.712 r90 top
R851 "100K" R0201 58.572,41.832 r180 top
R852 "100K" R0201 53.175,40.15 r180 top
R853 "100K" R0201 58.75,35.725 r180 top
R882 "220R" R0402 50.6,44.95 r270 top
R900 "2K05" R0201 89.25,54 r90 top
R902 "33R" R0402 37.625,38.75 r0 top
R903 "5K76" R0201 6.9,45.1 r180 top
R904 "33R" R0402 37.625,37.875 r0 top
R906 "10K" R0201 47.974,32.598 r270 top
R907 "4K7" R0201 50.85,46.75 r180 top
R908 "4K7" R0201 50.85,46.2 r180 top
R909 "10K" R0201 50.85,47.3 r180 top
R912 "2K15" R0201 16.7,42.8 r180 top
R919 "1K" R0201 14.922,45.531 r0 top
R920 "2K37" R0201 14.922,46.215 r0 top
R930 "1K" R0201 44.613,47.718 r180 top
R931 "1K" R0201 43.484,46.821 r90 top
R950 "100K" R0201 50.9,41.2 r270 top
R981 "100K" R0201 50.725,40.2 r0 top
R982 "10K" R0201 39.771,34.452 r0 top
RP800 "33R" RES_MNR04-8 50.125,37.5 r90 top
RP801 "33R" RES_MNR04-8 57.375,44.45 r90 top
ST701 "2X1 2.54MM" HDR_M254-1X2 2.875,2.08 r90 top
SW1 "PTS810" SW_CK_PTS810_SJM_250 99.642,36.739 r90 top
SW100 "PTS810" SW_CK_PTS810_SJM_250 98.75,8.948 r180 top
SW101 "PTS810" SW_CK_PTS810_SJM_250 86.75,8.948 r180 top
SW704 "SW_DP3T" CK_DP3T_JS203011SCQN 20.9,4.6 r0 top
T1 "TOUCH SLIDER" TOUCH_SLIDER2_28.0X7.0-4 31.2,9.9 r0 top
TAB1 "Comment" TAB_V-CUT_L7.0_W2.4 12,0.001 r180 top
TAB1_1 "Comment" TAB_V-CUT_L7.0_W2.4 12,0 r180 top
TAB2 "Comment" TAB_V-CUT_L7.0_W2.4 60,0 r180 top
TAB2_1 "Comment" TAB_V-CUT_L7.0_W2.4 60,0 r180 top
TAB3 "Comment" TAB_V-CUT_L7.0_W2.4 98,0 r180 top
TAB3_1 "Comment" TAB_V-CUT_L7.0_W2.4 98,0 r180 top
TAB4 "Comment" TAB_V-CUT_L7.0_W2.4 12,60 r0 top
TAB5 "Comment" TAB_V-CUT_L7.0_W2.4 60,60 r0 top
TAB5_1 "Comment" TAB_V-CUT_L7.0_W2.4 60,60 r0 top
TAB6 "Comment" TAB_V-CUT_L7.0_W2.4 98,60 r0 top
TAB6_1 "Comment" TAB_V-CUT_L7.0_W2.4 98,60 r0 top
TP156 "TP_SMD" TP_1.0_SMD 15.3,4.6 r180 bottom
TP400 "TP_SMD" TP_1.0_SMD 101.312,33.599 r180 bottom
TP700 "TP_SMD" TP_1.0_SMD 37.85,29.45 r180 bottom
TP701 "TP_SMD" TP_1.0_SMD 25.6,36.975 r180 bottom
TP703 "TP_SMD" TP_1.0_SMD 28.5,3.25 r180 bottom
TP705 "TP_SMD" TP_1.0_SMD 41.75,33.775 r180 bottom
TP706 "TP_SMD" TP_1.0_SMD 32.8,44.5 r180 bottom
TP707 "TP_SMD" TP_1.0_SMD 40.3,44.1 r180 bottom
TP708 "TP_SMD" TP_1.0_SMD 25.875,23.65 r180 bottom
TP709 "TP_SMD" TP_1.0_SMD 23.625,4.175 r180 bottom
TP711 "TP_SMD" TP_1.0_SMD 40.375,32.075 r180 bottom
TP712 "TP_SMD" TP_1.0_SMD 39.7,34.4 r180 bottom
TP713 "TP_SMD" TP_1.0_SMD 44.6,33 r180 bottom
TP714 "TP_SMD" TP_1.0_SMD 28.025,30.043 r180 bottom
TP715 "TP_SMD" TP_1.0_SMD 32.025,31.05 r180 bottom
TP923 "TP_SMD" TP_1.0_SMD 37.6,36.575 r180 bottom
TP930 "TP_SMD" TP_1.0_SMD 65.25,29.3 r180 bottom
TPJ402 "TP_SMD" TP_1.0_SMD 81.5,10.45 r180 bottom
TPJ403 "TP_SMD" TP_1.0_SMD 77.25,10.449 r180 bottom
TPJ404 "TP_SMD" TP_1.0_SMD 72.95,10.449 r180 bottom
TPJ405 "TP_SMD" TP_1.0_SMD 74.101,6.248 r180 bottom
TPJ600 "TP_SMD" TP_1.0_SMD 14.35,32.301 r180 bottom
TPJ606 "TP_SMD" TP_1.0_SMD 97.4,47.201 r180 bottom
TPJ607 "TP_SMD" TP_1.0_SMD 66.65,44.1 r180 bottom
TPJ608 "TP_SMD" TP_1.0_SMD 34.525,20.526 r180 bottom
TPJ611 "TP_SMD" TP_1.0_SMD 10.149,51.301 r180 bottom
TPJ612 "TP_SMD" TP_1.0_SMD 10.149,53.851 r180 bottom
TPJ613 "TP_SMD" TP_1.0_SMD 12.699,53.851 r180 bottom
TPJ614 "TP_SMD" TP_1.0_SMD 7.548,49.799 r180 bottom
TPJ650 "TP_SMD" TP_1.0_SMD 108.248,43.251 r180 bottom
TPJ651 "TP_SMD" TP_1.0_SMD 108.248,39.7 r180 bottom
TPJ652 "TP_SMD" TP_1.0_SMD 61.3,16.1 r180 bottom
TPJ653 "TP_SMD" TP_1.0_SMD 51.95,16.1 r180 bottom
TPJ811 "TP_SMD" TP_1.0_SMD 77.9,52.7 r180 bottom
TPJ812 "TP_SMD" TP_1.0_SMD 81.65,53.45 r180 bottom
TPJ814 "TP_SMD" TP_1.0_SMD 84.35,54.3 r180 bottom
TPJ817 "TP_SMD" TP_1.0_SMD 102.648,48.349 r180 bottom
TPJ818 "TP_SMD" TP_1.0_SMD 71.55,40.95 r180 bottom
TPJ820 "TP_SMD" TP_1.0_SMD 80.2,50.95 r180 bottom
TPJ900 "TP_SMD" TP_1.0_SMD 41.6,37.9 r180 bottom
TPJ901 "TP_SMD" TP_1.0_SMD 44.05,38.55 r180 bottom
TPJ902 "TP_SMD" TP_1.0_SMD 24.6,41.4 r180 bottom
TPJ908 "TP_SMD" TP_1.0_SMD 43.95,45.6 r180 bottom
TPJ909 "TP_SMD" TP_1.0_SMD 42.65,43.425 r180 bottom
TPJ910 "TP_SMD" TP_1.0_SMD 48,29.65 r180 bottom locked
TPJ911 "TP_SMD" TP_1.0_SMD 45.45,28.85 r180 bottom
TPJ912 "TP_SMD" TP_1.0_SMD 50.75,34.225 r180 bottom
TPJ913 "TP_SMD" TP_1.0_SMD 50.75,30.5 r180 bottom
TPJ950 "TP_SMD" TP_1.0_SMD 24.449,17.1 r180 bottom locked
TPJ953 "TP_SMD" TP_1.0_SMD 42,25.25 r180 bottom
TPJ954 "TP_SMD" TP_1.0_SMD 43.25,27.5 r180 bottom
TPJ955 "TP_SMD" TP_1.0_SMD 44.5,25.25 r180 bottom
TPJ956 "TP_SMD" TP_1.0_SMD 52.75,39.25 r180 bottom
TPJ957 "TP_SMD" TP_1.0_SMD 51.799,27.599 r180 bottom
TPJ958 "TP_SMD" TP_1.0_SMD 53.15,25.45 r180 bottom
TPJ959 "TP_SMD" TP_1.0_SMD 54.499,27.599 r180 bottom
TPJ960 "TP_SMD" TP_1.0_SMD 53.899,32.598 r90 bottom
TPJ961 "TP_SMD" TP_1.0_SMD 53.95,30.05 r180 bottom
U1 "EFM32WG990F256" BGA112_M080_10.0X10.0_SL 85.6,32.75 r0 top
U400 "AP2151" U-DFN2018-6_M050_2.0X1.8_EP 72.387,7.776 r270 top
U600 "LP3982ILD-ADJ" WSON8_M050_3.0X2.5_EP_TI_NGM 23.387,44.93 r90 top
U603 "TLV70536" DSBGA4_M040_0.8X0.8_TI_YFP 38.425,29.45 r180 top
U606 "MCP6001T" SC70-5 41.85,26.875 r180 top
U622 "MCP6001T" SC70-5 51.075,32.35 r180 top
U700 "SIP32431" TDFN4_M050_1.6X1.2_EP_VISH 27.375,29.75 r90 top
U701 "LP3982ILD-ADJ" WSON8_M050_3.0X2.5_EP_TI_NGM 33.975,27.9 r270 top
U702 "TS3A4751" QFN14_M040_2.0X2.0_TI_RUC 36.775,33.675 r180 top
U703 "LTC6102CDD" DFN8_M050_3.0X3.0_EP_LT_DD 31.725,36.3 r180 top
U704 "AD8656" MSOP8_M065_W3.0 30.525,41 r0 top
U800 "74LVC4066" DHVQFN14_M050_2.5X3_EP_NXP 61.575,44.5 r270 top
U802 "74LVC4066" DHVQFN14_M050_2.5X3_EP_NXP 61.575,40 r270 top
U803 "74LVC1T45" X2-DFN1010-6_M035_DIODES 65.8,41.4 r0 top
U804 "74LVC2G125" DSBGA8_M050_0.9X1.9_TI_YZP 47.55,35.45 r180 top
U805 "TS3A4751" QFN14_M040_2.0X2.0_TI_RUC 55.45,37.97 r90 top
U806 "74LVC4066" DHVQFN14_M050_2.5X3_EP_NXP 61.575,35.5 r270 top
U807 "74LVC1T45" X2-DFN1010-6_M035_DIODES 66.03,35.66 r0 top
U808 "74LVC8T245" VQFN24_M050_3.5X5.5_EP_TI_RHL 54.075,43.95 r0 top
U809 "74LVC2G125" DSBGA8_M050_0.9X1.9_TI_YZP 47.575,38.675 r180 top
U810 "74LVC4066" DHVQFN14_M050_2.5X3_EP_NXP 61.575,31 r270 top
U812 "TS3A4751" QFN14_M040_2.0X2.0_TI_RUC 57.775,30.95 r90 top
U860 "74LVC1T45" X2-DFN1010-6_M035_DIODES 48.024,45.009 r180 top
U861 "74LVC1T45" X2-DFN1010-6_M035_DIODES 58.275,40.8 r90 top
U862 "74LVC1T45" X2-DFN1010-6_M035_DIODES 53.125,39.1 r90 top
U863 "74LVC1T45" X2-DFN1010-6_M035_DIODES 58.375,34.7 r90 top
U900 "EFM32GG12B410F1024GL120-A" BGA120_M050_7.0X7.0_EFM32GGR 42.675,41.025 r180 top
U901 "M24C02" TDFN8_M050_2.0X3.0_EP 47.825,47 r0 top
U902 "MX25R8035F" BGA8_M040_1.24X1.75_WLCSP 46.925,32.3 r0 top
U910 "ADC084S021" VSSOP10_M050_W3.0_TI_DGS 42.5,32.025 r0 top
U950 "TS3A4751" QFN14_M040_2.0X2.0_TI_RUC 49.2,41.9 r270 top
X1 "48 MHz" X_KDS_DSX211SH_2.0X1.65-4 87.725,25.975 r180 top
X2 "32.768kHz" X_TAI-SAW-TZ2528C_2.05X1.2-2 79.35,29.175 r90 top
X900 "48 MHz" X_KDS_DSX211SH_2.0X1.65-4 41.675,46.3 r0 top
? "Comment" LOGO_EFM32_W18.0 75.232,44.5 r0 top locked

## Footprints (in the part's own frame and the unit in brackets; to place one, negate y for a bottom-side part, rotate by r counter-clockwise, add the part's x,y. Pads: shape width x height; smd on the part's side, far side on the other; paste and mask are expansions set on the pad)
BAT_HOLD_MPD_BK-912_CR2032 [mil] "MPD Battery Holder BK-912 (for CR2032)"
  rrect20% 110x200 smd: 1(-430,0) 1(430,0)
  round 157.48 smd paste-295.67 mask-82.68: 2(0,0)
  body extent -450,-394 450,394, height 171
BAT_SEIKO_XH311HG [mm] "Micro Battery Seiko XH311HG IV01E (Dia 3.8) (170308)"
  rrect20% 0.1x0.1 smd paste-0.1 mask-0.1: 1(1.7,-1.7)
  rrect20% 1x2.8 smd: 2(-1.6,-0.7)
  Top Layer region: 2.093,-2.04 2.093,-0.726 2.093,-0.715 2.082,-0.699 2.063,-0.691 2.043,-0.695 2.036,-0.702 2.036,-0.702 0.694,-2.044 0.687,-2.051 0.683,-2.071 0.69,-2.089 0.707,-2.1 0.717,-2.1 0.717,-2.1 2.033,-2.1 2.045,-2.1 2.067,-2.091 2.084,-2.074 2.093,-2.052 2.093,-2.04
  Top Layer keep-out region: -0.9,-2.1 0.4,-2.1 2,-0.5 2,0.641 2,0.775 1.948,1.038 1.845,1.285 1.697,1.508 1.508,1.697 1.285,1.845 1.038,1.948 0.775,2 0.641,2 0.641,2 -0.7,2 -0.808,2 -1.021,1.958 -1.221,1.875 -1.401,1.754 -1.554,1.601 -1.675,1.421 -1.758,1.221 -1.8,1.008 -1.8,0.9 -1.8,0.9 -0.9,0.9
  body extent -1.9,-1.9 1.9,1.9, height 1.1
BGA8_M040_1.24X1.75_WLCSP [mm] "BGA, 8 pin. U100"
  round 0.21 smd mask+0.05: A1(-0.35,0.4) A3(0.35,0.4) B2(0,0.2) C1(-0.35,0) C3(0.35,0) D2(0,-0.2) E1(-0.35,-0.4) E3(0.35,-0.4)
  body extent -0.63,-0.89 0.63,0.88, height 0.52
BGA112_M080_10.0X10.0_SL [mm] "BGA, 112-Leads, Body 10.0x10.0x1.3, Pitch 0,80 (190314)"
  round 0.35 smd: A1(-4,4) A2(-3.2,4) A3(-2.4,4) A4(-1.6,4) A5(-0.8,4) A6(0,4) A7(0.8,4) A8(1.6,4) A9(2.4,4) A10(3.2,4) A11(4,4) B1(-4,3.2) B2(-3.2,3.2) B3(-2.4,3.2) B4(-1.6,3.2) B5(-0.8,3.2) B6(0,3.2) B7(0.8,3.2) B8(1.6,3.2) B9(2.4,3.2) B10(3.2,3.2) B11(4,3.2) C1(-4,2.4) C2(-3.2,2.4) C3(-2.4,2.4) C4(-1.6,2.4) C5(-0.8,2.4) C6(0,2.4) C7(0.8,2.4) C8(1.6,2.4) C9(2.4,2.4) C10(3.2,2.4) C11(4,2.4) D1(-4,1.6) D2(-3.2,1.6) D3(-2.4,1.6) D4(-1.6,1.6) D5(-0.8,1.6) D6(0,1.6) D7(0.8,1.6) D8(1.6,1.6) D9(2.4,1.6) D10(3.2,1.6) D11(4,1.6) E1(-4,0.8) E2(-3.2,0.8) E3(-2.4,0.8) E4(-1.6,0.8) E8(1.6,0.8) E9(2.4,0.8) E10(3.2,0.8) E11(4,0.8) F1(-4,0) F2(-3.2,0) F3(-2.4,0) F4(-1.6,0) F8(1.6,0) F9(2.4,0) F10(3.2,0) F11(4,0) G1(-4,-0.8) G2(-3.2,-0.8) G3(-2.4,-0.8) G4(-1.6,-0.8) G8(1.6,-0.8) G9(2.4,-0.8) G10(3.2,-0.8) G11(4,-0.8) H1(-4,-1.6) H2(-3.2,-1.6) H3(-2.4,-1.6) H4(-1.6,-1.6) H5(-0.8,-1.6) H6(0,-1.6) H7(0.8,-1.6) H8(1.6,-1.6) H9(2.4,-1.6) H10(3.2,-1.6) H11(4,-1.6) J1(-4,-2.4) J2(-3.2,-2.4) J3(-2.4,-2.4) J4(-1.6,-2.4) J5(-0.8,-2.4) J6(0,-2.4) J7(0.8,-2.4) J8(1.6,-2.4) J9(2.4,-2.4) J10(3.2,-2.4) J11(4,-2.4) K1(-4,-3.2) K2(-3.2,-3.2) K3(-2.4,-3.2) K4(-1.6,-3.2) K5(-0.8,-3.2) K6(0,-3.2) K7(0.8,-3.2) K8(1.6,-3.2) K9(2.4,-3.2) K10(3.2,-3.2) K11(4,-3.2) L1(-4,-4) L2(-3.2,-4) L3(-2.4,-4) L4(-1.6,-4) L5(-0.8,-4) L6(0,-4) L7(0.8,-4) L8(1.6,-4) L9(2.4,-4) L10(3.2,-4) L11(4,-4)
  body extent -5,-5 5,5, height 1.3
BGA120_M050_7.0X7.0_EFM32GGR [mm] "BGA, 120 Leads, Body 7.0x7.0mmx1,30mm, Pitch 0.50mm (191111)"
  round 0.2 smd mask+0.04: A1(-3,3) A2(-2.5,3) A3(-2,3) A4(-1.5,3) A5(-1,3) A6(-0.5,3) A7(0,3) A8(0.5,3) A9(1,3) A10(1.5,3) A11(2,3) A12(2.5,3) A13(3,3) B1(-3,2.5) B2(-2.5,2.5) B3(-2,2.5) B4(-1.5,2.5) B5(-1,2.5) B6(-0.5,2.5) B7(0,2.5) B8(0.5,2.5) B9(1,2.5) B10(1.5,2.5) B11(2,2.5) B12(2.5,2.5) B13(3,2.5) C1(-3,2) C2(-2.5,2) C3(-2,2) C4(-1.5,2) C5(-1,2) C6(-0.5,2) C7(0,2) C8(0.5,2) C9(1,2) C10(1.5,2) C11(2,2) C12(2.5,2) C13(3,2) D1(-3,1.5) D2(-2.5,1.5) D3(-2,1.5) D11(2,1.5) D12(2.5,1.5) D13(3,1.5) E1(-3,1) E2(-2.5,1) E3(-2,1) E11(2,1) E12(2.5,1) E13(3,1) F1(-3,0.5) F2(-2.5,0.5) F3(-2,0.5) F11(2,0.5) F12(2.5,0.5) F13(3,0.5) G1(-3,0) G2(-2.5,0) G3(-2,0) G11(2,0) G12(2.5,0) G13(3,0) H1(-3,-0.5) H2(-2.5,-0.5) H3(-2,-0.5) H11(2,-0.5) H12(2.5,-0.5) H13(3,-0.5) J1(-3,-1) J2(-2.5,-1) J3(-2,-1) J11(2,-1) J12(2.5,-1) J13(3,-1) K1(-3,-1.5) K2(-2.5,-1.5) K3(-2,-1.5) K11(2,-1.5) K12(2.5,-1.5) K13(3,-1.5) L1(-3,-2) L2(-2.5,-2) L3(-2,-2) L4(-1.5,-2) L5(-1,-2) L6(-0.5,-2) L7(0,-2) L8(0.5,-2) L9(1,-2) L10(1.5,-2) L11(2,-2) L12(2.5,-2) L13(3,-2) M1(-3,-2.5) M2(-2.5,-2.5) M3(-2,-2.5) M4(-1.5,-2.5) M5(-1,-2.5) M6(-0.5,-2.5) M7(0,-2.5) M8(0.5,-2.5) M9(1,-2.5) M10(1.5,-2.5) M11(2,-2.5) M12(2.5,-2.5) M13(3,-2.5) N1(-3,-3) N2(-2.5,-3) N3(-2,-3) N4(-1.5,-3) N5(-1,-3) N6(-0.5,-3) N7(0,-3) N8(0.5,-3) N9(1,-3) N10(1.5,-3) N11(2,-3) N12(2.5,-3) N13(3,-3)
  body extent -3.5,-3.5 3.5,3.5, height 1.3
C0201 [mm] "Capacitor, 9291, HiDens (170502)"
  rrect25% 0.36x0.32 smd paste-0.015: 1(-0.275,0) 2(0.275,0)
  Top Layer pour cut-out: -0.075,-0.2 -0.075,0.2 0.075,0.2 0.075,-0.2
  body extent -0.32,-0.13 0.32,0.13, height 0.3
C0402 [mm] "Chip Capacitor, 2-Leads, Body 1.0x0.5mm, IPC High Density (190308)"
  rrect20% 0.5x0.5 smd mask+0.051: 1(-0.5,0) 2(0.5,0)
  Top Layer pour cut-out: -0.225,-0.3 -0.225,0.3 0.225,0.3 0.225,-0.3
  body extent -0.5,-0.25 0.5,0.25, height 0.6
C0603 [mm] "Capacitor, 0603, HiDens (190130)"
  rrect25% 0.8x0.85 smd: 1(-0.7,0) 2(0.7,0)
  Top Layer pour cut-out: -0.275,-0.55 -0.275,0.55 0.275,0.55 0.275,-0.55
  body extent -0.88,-0.48 0.87,0.48, height 0.95
CK_DP3T_JS203011SCQN [mm] "Switch, C & K DP3T JS203011SCQN (190314)"
  rrect50% 1.2x2.5 smd: 1(-4,-2.75) 2(-2,-2.75) 3(2,-2.75) 4(4,-2.75) 5(-4,2.75) 6(-2,2.75) 7(2,2.75) 8(4,2.75)
  body extent -6.5,-3.75 6.5,3.75, height 5.22
COIL_0402 [mm] "COIL_0402_L (3D from Wurth) (190308)"
  rrect20% 0.55x0.5 smd mask+0.051: 1(-0.525,0) 2(0.525,0)
  body extent -0.5,-0.25 0.5,0.25, height 0.5
COIL_BOURNS_SDR0302 [mm] "Coil Bourns SDR0302 D 3.0 H2.5 (190312)"
  rect 1.4x2 smd: 1(-1.1,0) 2(1.1,0)
  Top Layer region: -1.8,0.7 -1.8,1.175 -1.8,1.24 -1.751,1.359 -1.659,1.451 -1.54,1.5 -1.475,1.5 -1.475,1.5 -0.425,1.5 -0.42,1.5 -0.411,1.496 -0.404,1.489 -0.4,1.48 -0.4,1.475 -0.4,1.475 -0.4,0.7
  Top Layer region: 1.8,0.7 1.8,1.175 1.8,1.24 1.751,1.359 1.659,1.451 1.54,1.5 1.475,1.5 1.475,1.5 0.425,1.5 0.42,1.5 0.411,1.496 0.404,1.489 0.4,1.48 0.4,1.475 0.4,1.475 0.4,0.7
  Top Layer region: -1.8,-0.7 -1.8,-1.175 -1.8,-1.24 -1.751,-1.359 -1.659,-1.451 -1.54,-1.5 -1.475,-1.5 -1.475,-1.5 -0.425,-1.5 -0.42,-1.5 -0.411,-1.496 -0.404,-1.489 -0.4,-1.48 -0.4,-1.475 -0.4,-1.475 -0.4,-0.7
  Top Layer region: 1.8,-0.7 1.8,-1.175 1.8,-1.24 1.751,-1.359 1.659,-1.451 1.54,-1.5 1.475,-1.5 1.475,-1.5 0.425,-1.5 0.42,-1.5 0.411,-1.496 0.404,-1.489 0.4,-1.48 0.4,-1.475 0.4,-1.475 0.4,-0.7
  body extent -1.5,-1.5 1.5,1.5, height 2.8
COIL_WURTH_CBF_0603 [mm] "COIL_WURTH_CBF_0603 (= L0603_0.8_L) (181031)"
  rrect10% 0.67x0.88 smd: 1(-0.665,0) 2(0.665,0)
  body extent -0.87,-0.48 0.87,0.48, height 0.95
DFN8_M050_3.0X3.0_EP_LT_DD [mm] "DFN 8 Lead, Pitch 0.5, 3.0x3.0x0.75 Exposed Pad, Linear Tech (171004)"
  rrect50% 0.7x0.25 smd paste-0.025 mask+0.07: 1(-1.4,0.75) 2(-1.4,0.25) 3(-1.4,-0.25) 4(-1.4,-0.75) 5(1.4,-0.75) 6(1.4,-0.25) 7(1.4,0.25) 8(1.4,0.75)
  rect 1x1.8 smd paste-1 mask+0: 9(0,0)
  Top Layer region: 0.825,1.2 -0.693,1.2 -0.825,1.095 -0.825,-1.2 0.825,-1.2
  body extent -1.56,-1.55 1.56,1.55, height 0.8
DFN2111-7_M050_1.2X2.1_NXP [mm] "DFN2111-7 NXP Pitch 035 1.2x2.1x0.5, NXP (190312)"
  rrect20% 0.53x0.19 smd mask+0.05: 1(-0.415,0.75) 2(-0.415,0.25) 3(-0.415,-0.25) 4(-0.415,-0.75) 5(0.415,-0.5) 6(0.415,0) 7(0.415,0.5)
  body extent -0.6,-1.05 0.6,1.05, height 0.51
DHVQFN14_M050_2.5X3_EP_NXP [mm] "DHVQFN, 14 Leads, 2.5x3.0x0.85, Pitch 0.50, Thermal Pad 1.0x1.5 (190314)"
  oval 0.3x0.7 smd: 1(-0.25,1.45) 7(-0.25,-1.45) 8(0.25,-1.45) 14(0.25,1.45)
  oval 0.7x0.3 smd: 2(-1.2,1) 3(-1.2,0.5) 4(-1.2,0) 5(-1.2,-0.5) 6(-1.2,-1) 9(1.2,-1) 10(1.2,-0.5) 11(1.2,0) 12(1.2,0.5) 13(1.2,1)
  rrect10% 1x1.5 smd: 17(0,0)
  body extent -1.25,-1.5 1.25,1.5, height 1.1
DSBGA4_M040_0.8X0.8_TI_YFP [mm] "DS-BGA, 4 Leads, Body 0.8x0.8 H:0.5, Pitch 0.40"
  round 0.23 smd mask+0.04: A1(-0.2,0.2) A2(0.2,0.2) B1(-0.2,-0.2) B2(0.2,-0.2)
  body extent -0.4,-0.4 0.4,0.4, height 0.51
DSBGA8_M050_0.9X1.9_TI_YZP [mm] "DS-BGA, 8 Leads, Body 0.9x1.9 H:0.5, Pitch 0.50"
  round 0.23 smd: A1(-0.25,0.75) A2(0.25,0.75) B1(-0.25,0.25) B2(0.25,0.25) C1(-0.25,-0.25) C2(0.25,-0.25) D1(-0.25,-0.75) D2(0.25,-0.75)
  body extent -0.45,-0.95 0.45,0.95, height 0.51
FCI_10137065_USB-C_RCPT_A1 [mm] "FCI AMPHENOL 10137065 USB-C Receptacle (Slot PinInPaste) (180404), extra paste added for solder leg to form proper fillet"
  oval 1.8x3.1 hole 0.7 slot 2 at 90 deg: 25(-4.32,-3.05)
  oval 1.3x2.6 on Top Paste: 25(-4.32,-3.05) 26(4.32,-3.05)
  oval 1.8x3.1 hole 0.7 slot 2 at 90 deg paste+0: 26(4.32,-3.05)
  oval 1.2x2.489 on Top Paste: 27(-4.32,2)
  oval 1.2x2.5 hole 0.6 slot 1.9 at 90 deg paste+0: 27(-4.32,2)
  oval 1.638x1.194 on Top Paste: 27(-4.025,1.35)
  oval 1.647x1.2 hole 0.6 slot 1.247 at 0 deg: 27(-4.025,1.35)
  oval 1.847x1.2 hole 0.6 slot 1.247 at 0 deg: 28(4.025,1.35)
  oval 1.841x1.194 on Top Paste: 28(4.025,1.35)
  oval 1.2x2.5 hole 0.6 slot 1.9 at 90 deg: 28(4.32,2)
  oval 1.194x2.489 on Top Paste: 28(4.32,2)
  rrect20% 0.27x0.9 smd mask+0.076: A1(-2.625,2.7) A2(-2.125,2.7) A3(-1.625,2.7) A4(-1.125,2.7) A5(-0.625,2.7) A6(-0.125,2.7) A7(0.375,2.7) A8(0.875,2.7) A9(1.375,2.7) A10(1.875,2.7) A11(2.375,2.7) A12(2.875,2.7)
  rrect20% 0.27x0.8 smd mask+0.076: B1(2.625,1.1) B2(2.125,1.1) B3(1.625,1.1) B4(1.125,1.1) B5(0.625,1.1) B6(0.125,1.1) B7(-0.375,1.1) B8(-0.875,1.1) B9(-1.375,1.1) B10(-1.875,1.1) B11(-2.375,1.1) B12(-2.875,1.1)
  round 0 hole 0.6 unplated mask+0.102: M1(-3.6,0)
  round 0 hole 0.5 slot 0.85 at 0 deg unplated mask+0.102: M2(3.6,0)
  Top Layer region: -4.32,-4.6 -4.664,-4.531 -4.956,-4.336 -5.151,-4.044 -5.22,-3.7 -5.22,-3.7 -5.22,-2.4 -5.151,-2.056 -4.956,-1.764 -4.664,-1.569 -4.32,-1.5 -4.32,-1.5 -3.976,-1.569 -3.684,-1.764 -3.489,-2.056 -3.42,-2.4 -3.42,-2.4 -3.42,-3.7 -3.489,-4.044 -3.684,-4.336 -3.976,-4.531 -4.32,-4.6
  Top Layer region: 4.32,-4.6 3.976,-4.531 3.684,-4.336 3.489,-4.044 3.42,-3.7 3.42,-3.7 3.42,-2.4 3.489,-2.056 3.684,-1.764 3.976,-1.569 4.32,-1.5 4.32,-1.5 4.664,-1.569 4.956,-1.764 5.151,-2.056 5.22,-2.4 5.22,-2.4 5.22,-3.7 5.151,-4.044 4.956,-4.336 4.664,-4.531 4.32,-4.6
  Top Layer region: -5.22,1.35 -5.22,3.606 -5.174,3.836 -5.044,4.031 -4.85,4.161 -4.62,4.206 -4.62,4.206 -4.02,4.206 -3.79,4.161 -3.596,4.031 -3.466,3.836 -3.42,3.606 -3.42,3.606 -3.42,1.35 -3.466,1.12 -3.596,0.926 -3.79,0.796 -4.02,0.75 -4.02,0.75 -4.62,0.75 -4.85,0.796 -5.044,0.926 -5.174,1.12 -5.22,1.35
  Top Layer region: 3.42,1.35 3.42,3.606 3.466,3.836 3.596,4.031 3.79,4.161 4.02,4.206 4.02,4.206 4.62,4.206 4.85,4.161 5.044,4.031 5.174,3.836 5.22,3.606 5.22,3.606 5.22,1.35 5.174,1.12 5.044,0.926 4.85,0.796 4.62,0.75 4.62,0.75 4.02,0.75 3.79,0.796 3.596,0.926 3.466,1.12 3.42,1.35
  Top Layer keep-out region: -3.9,-4.85 3.9,-4.85 3.9,0.4 -3.9,0.4
  body extent -4.47,-5.3 4.47,2.85, height 3.14
HDR_M254-1X2 [mm] "Connector; Header; 2 Position (170508)"
  round 1.6 hole 1: 1(0,0) 2(2.54,0)
  body extent -1.07,-1.17 3.61,1.17, height 8.12
HDR_M254_RING-2X16 [mm] "Connector; Header; 2x16 Position, 2.54mm (190312)"
  round 1.6 hole 1: 1(-19.05,-1.27) 2(-19.05,1.27) 3(-16.51,-1.27) 4(-16.51,1.27) 5(-13.97,-1.27) 6(-13.97,1.27) 7(-11.43,-1.27) 8(-11.43,1.27) 9(-8.89,-1.27) 10(-8.89,1.27) 11(-6.35,-1.27) 12(-6.35,1.27) 13(-3.81,-1.27) 14(-3.81,1.27) 15(-1.27,-1.27) 16(-1.27,1.27) 17(1.27,-1.27) 18(1.27,1.27) 19(3.81,-1.27) 20(3.81,1.27) 21(6.35,-1.27) 22(6.35,1.27) 23(8.89,-1.27) 24(8.89,1.27) 25(11.43,-1.27) 26(11.43,1.27) 27(13.97,-1.27) 28(13.97,1.27) 29(16.51,-1.27) 30(16.51,1.27) 31(19.05,-1.27) 32(19.05,1.27)
HDR_SULLINS_M127_PEG-2X10 [mil] "Sullins, GRPB102VQS (180319)"
  rrect50% 30x87 smd: 1(-25,-72.5) 2(-25,72.5) 3(25,-72.5) 4(25,72.5) 5(75,-72.5) 6(75,72.5) 7(125,-72.5) 8(125,72.5) 9(175,-72.5) 10(175,72.5) 11(225,-72.5) 12(225,72.5) 13(275,-72.5) 14(275,72.5) 15(325,-72.5) 16(325,72.5) 17(375,-72.5) 18(375,72.5) 19(425,-72.5) 20(425,72.5)
  round 0 hole 39.37 unplated mask+3.94: M1(0,0) M2(400,0)
  body extent -50,-100 450,101, height 197
HOLE_3.0_5.0_PL [mm] "Hole 3.0 mm, Plated (171122)"
  round 5 hole 3: 1(0,0)
HOLE_3.0_NPL [mm] "HOLE_3.0_NPL (170815)"
  round 0 hole 3 unplated mask+0.2: 1(0,0)
  body extent -1.5,-1.5 1.5,1.5
KLS_KLS1-5245 [mm] "Micro USB 5P Femalw type AB"
  rrect20% 0.35x1.7 smd mask+0.076: 1(-1.3,4.85) 2(-0.65,4.85) 3(0,4.85) 4(0.65,4.85) 5(1.3,4.85)
  rrect50% 1.3x1.55 hole 0.55 slot 0.75 at 0 deg: 6(-2.225,5.05) 7(2.225,5.05)
  rrect50% 1.656x2.357 hole 0.5 slot 1.1 at 90 deg: 8(-4.175,2.15) 9(4.175,2.15)
  Top Layer region: -5.003,1.427 -5.003,2.874 -4.968,3.048 -4.87,3.195 -4.722,3.294 -4.548,3.329 -4.548,3.329 -3.802,3.329 -3.628,3.294 -3.48,3.195 -3.382,3.048 -3.347,2.874 -3.347,2.874 -3.347,1.427 -3.382,1.252 -3.48,1.105 -3.628,1.006 -3.802,0.972 -3.802,0.972 -4.548,0.972 -4.722,1.006 -4.87,1.105 -4.968,1.252 -5.003,1.427
  Top Layer region: 3.347,1.427 3.347,2.874 3.382,3.048 3.48,3.195 3.628,3.294 3.802,3.329 3.802,3.329 4.548,3.329 4.722,3.294 4.87,3.195 4.968,3.048 5.003,2.874 5.003,2.874 5.003,1.427 4.968,1.252 4.87,1.105 4.722,1.006 4.548,0.972 4.548,0.972 3.802,0.972 3.628,1.006 3.48,1.105 3.382,1.252 3.347,1.427
  Top Layer region: 1.675,4.578 1.675,5.522 1.706,5.68 1.796,5.814 1.93,5.904 2.088,5.935 2.088,5.935 2.762,5.935 2.92,5.904 3.054,5.814 3.144,5.68 3.175,5.522 3.175,5.522 3.175,4.578 3.144,4.42 3.054,4.286 2.92,4.196 2.762,4.165 2.762,4.165 2.088,4.165 1.93,4.196 1.796,4.286 1.706,4.42 1.675,4.578
  Top Layer region: -1.675,4.578 -1.675,5.522 -1.706,5.68 -1.796,5.814 -1.93,5.904 -2.088,5.935 -2.088,5.935 -2.762,5.935 -2.92,5.904 -3.054,5.814 -3.143,5.68 -3.175,5.522 -3.175,5.522 -3.175,4.578 -3.143,4.42 -3.054,4.286 -2.92,4.196 -2.762,4.165 -2.762,4.165 -2.088,4.165 -1.93,4.196 -1.796,4.286 -1.706,4.42 -1.675,4.578
  body extent -4.02,-0.53 4.03,5.27, height 3.1
LABEL_4CORNERS_19.0X6.0 [mm]
  silkscreen extent -9.5,-3 9.5,3
LCD_TRI-T_CL010-1087-03 [mm] "LCD_TRI-T_CL010-1087-03 (190320)"
  round 1.4 hole 0.8: 1(-13,-12.7) 2(-11,-12.7) 3(-9,-12.7) 4(-7,-12.7) 5(-5,-12.7) 6(-3,-12.7) 7(-1,-12.7) 8(1,-12.7) 9(3,-12.7) 10(5,-12.7) 11(7,-12.7) 12(9,-12.7) 13(11,-12.7) 14(13,-12.7) 15(13,12.7) 16(11,12.7) 17(9,12.7) 18(7,12.7) 19(5,12.7) 20(3,12.7) 21(1,12.7) 22(-1,12.7) 23(-3,12.7) 24(-5,12.7) 25(-7,12.7) 26(-9,12.7) 27(-11,12.7) 28(-13,12.7)
LED_0402 [mm] "Chip Diode, 2-Leads, Body 1.00x0.50mm, IPC High Density (170127)"
  rrect10% 0.45x0.6 smd: 1(-0.45,0) 2(0.45,0)
  body extent -0.55,-0.33 0.55,0.33, height 0.25
LED_0402_CAT2 [mm] "(200921)"
  rrect10% 0.45x0.6 smd: 1(-0.45,0) 2(0.45,0)
  body extent -0.55,-0.33 0.55,0.33, height 0.25
LED_AVAGO_HSMF-C165-4 [mm] "LED (dual) Avago HSMF-C165 Grn+Red 1.6x0.8x0.5 (200226)"
  rrect20% 0.7x0.4 smd: 1(-0.65,-0.35) 2(-0.65,0.35) 3(0.65,0.35) 4(0.65,-0.35)
  body extent -0.8,-0.4 0.8,0.4, height 0.52
LOGO_EFM32_W18.0 [mm]
  silkscreen extent 12.4,0.08 18.08,2.31
LOGO_GECKO_H6.0 [mm] "Silicon Labs, Gecko logo"
  silkscreen extent 0.03,0.04 5.31,6.01
LOGO_SEGGER_10.0X5.0_SM [mm] "Logo, Segger 10.0x5.0, Top Solder + M19 + Top Overlay"
LOGO_SILABS_W18.0 [mm]
  silkscreen extent 0.02,0.02 16.98,8.32
MSOP8_M065_W3.0 [mm] "MSOP, 8-Leads, Body 3.0x3.0mm, Pitch 0.65mm (170921)"
  rrect20% 0.889x0.42 smd mask+0.048: 1(-2.105,0.975) 2(-2.105,0.325) 3(-2.105,-0.325) 4(-2.105,-0.975) 5(2.106,-0.975) 6(2.106,-0.325) 7(2.106,0.325) 8(2.106,0.975)
  body extent -1.55,-1.55 1.55,1.55, height 1.11
QFN14_M040_2.0X2.0_TI_RUC [mm] "QFN 14 Leads, Pitch 0.4 mm, 2.0 x 2.0 H: 0.37, TI: RUC (180613)"
  rrect20% 0.68x0.2 smd: 1(-0.885,0.8) 2(-0.885,0.4) 3(-0.885,0) 4(-0.885,-0.4) 5(-0.885,-0.8) 8(0.885,-0.8) 9(0.885,-0.4) 10(0.885,0) 11(0.885,0.4) 12(0.885,0.8)
  rrect20% 0.2x0.68 smd: 6(-0.2,-0.885) 7(0.2,-0.885) 13(0.2,0.885) 14(-0.2,0.885)
  body extent -1,-1 1,1, height 0.41
R0201 [mm] "Resistor (Chip2PinSM127P600-8N) (170921)"
  rrect25% 0.34x0.32 smd: 1(-0.3,0) 2(0.3,0)
  Top Layer pour cut-out: -0.1,-0.2 -0.1,0.2 0.1,0.2 0.1,-0.2
  body extent -0.32,-0.13 0.32,0.13, height 0.3
R0402 [mm] "Chip Resistor, 2-Leads, Body 1.0x0.5mm, HiDens (190308)"
  rrect20% 0.6x0.6 smd mask+0.051: 1(-0.45,0) 2(0.45,0)
  Top Layer pour cut-out: -0.125,-0.3 -0.125,0.3 0.125,0.3 0.125,-0.3
  body extent -0.5,-0.25 0.5,0.25, height 0.6
R0603 [mm] "Chip Resistor, 0603, HiDens (190130)"
  rrect25% 0.85x0.9 smd: 1(-0.7,0) 2(0.7,0)
  Top Layer pour cut-out: -0.25,-0.575 -0.25,0.575 0.25,0.575 0.25,-0.575
  body extent -0.88,-0.48 0.87,0.48, height 0.95
R1206 [mm] "Resistor, 1206, HiDens (191114)"
  rrect25% 0.85x1.65 smd paste-0.04 mask+0.07: 1(-1.425,0) 2(1.425,0)
  body extent -1.6,-0.8 1.6,0.8, height 1
RES_MNR04-8 [mm] "Resistor Array, ROHM MNR04 8-Pin 2.0x1.0x0.35 (!80615)"
  rrect20% 0.4x0.5 smd: 1(-0.75,-0.45) 4(0.75,-0.45) 5(0.75,0.45) 8(-0.75,0.45)
  rrect20% 0.3x0.5 smd: 2(-0.25,-0.45) 3(0.25,-0.45) 6(0.25,0.45) 7(-0.25,0.45)
  body extent -1,-0.4 1,0.4, height 0.5
SC70-5 [mm] "SC70-5 = SOT353, HiDens (170511)"
  rrect25% 0.6x0.4 smd paste-0.03 mask+0.05: 1(-0.95,0.65) 2(-0.95,0) 3(-0.95,-0.65) 4(0.95,-0.65) 5(0.95,0.65)
  body extent -1.12,-0.97 1.16,1.03, height 0.95
SOT563 [mm] "SOT563 (_M050_W1.2_), 6-Leads, Body 1.60x1.20, Pitch 0.5, HiDens (170926)"
  rrect25% 0.6x0.3 smd: 1(-0.65,0.5) 2(-0.65,0) 3(-0.65,-0.5) 4(0.65,-0.5) 5(0.65,0) 6(0.65,0.5)
  body extent -0.65,-0.85 0.65,0.85, height 0.6
SOT563_DIODES [mm] "SOT563 (_M050_W1.2_), 6-Leads, Body 1.60x1.20, Pitch 0.5, HiDens (170926)"
  rrect25% 0.5x0.375 smd: 1(-0.85,0.5) 2(-0.85,0) 3(-0.85,-0.5) 4(0.85,-0.5) 5(0.85,0) 6(0.85,0.5)
  body extent -0.66,-0.85 0.65,0.85, height 0.6
SW_CK_PTS810_SJM_250 [mm] "Switch C&K PTS810_SJM_250 (grey button) (180319)"
  rrect20% 1.05x0.65 smd: 1(-2.075,1.075) 2(2.075,1.075) 3(-2.075,-1.075) 4(2.075,-1.075)
  body extent -2.29,-1.6 2.29,1.6, height 2.5
TAB_V-CUT_L7.0_W2.4 [mm] "TAB V_CUT, Length 7.0, Width 2.4"
TDFN4_M050_1.6X1.2_EP_VISH [mm] "TDFN, 4-Leads, Body 1.60x1.20mm, IPC HiDens (180111)"
  rrect10% 0.55x0.3 smd: 1(-0.725,0.25) 2(-0.725,-0.25) 3(0.725,-0.25) 4(0.725,0.25)
  rrect10% 0.5x0.86 smd paste-0.05: 5(0,0)
  body extent -0.8,-0.6 0.8,0.6, height 0.61
TDFN8_M050_2.0X3.0_EP [mm] "TDFN8_M050_2.0x3.0_EP (170921)"
  rrect20% 0.75x0.3 smd: 1(-1.45,0.75) 2(-1.45,0.25) 3(-1.45,-0.25) 4(-1.45,-0.75) 5(1.45,-0.75) 6(1.45,-0.25) 7(1.45,0.25) 8(1.45,0.75)
  rrect10% 1.5x1.4 smd: 9(0,0)
  body extent -1.5,-1 1.5,1, height 1.01
TEMT6200FX01_GEN_0805 [mm] "Phototransistor, 0805"
  rrect25% 0.95x1.35 smd: 1(-0.8,0) 2(0.8,0)
  body extent -1.17,-0.77 1.15,0.77, height 1.45
TOUCH_SLIDER2_28.0X7.0-4 [mm] "TOUCH_SLIDER2_28.0X7.0-4 (170306)"
  round 1 smd paste-0.51 mask-0.51: 1(1.424,3.924) 2(11.4,4) 3(19.5,4) 4(27.6,4)
  Top Layer region: 7.4,7.5 1.6,7.5 0.5,7.5 0.5,4 0.5,0.5 1.6,0.5 7.4,0.5 7.4,0.7 1.9,2 7.7,3.9 7.7,4.1 1.938,6 7.4,7.3
  Top Layer region: 15.7,7.5 9.9,7.5 3.8,6 3.8,5.8 9.4,4 3.8,2.2 3.8,2 9.9,0.5 15.7,0.5 15.7,0.7 10.2,2 16,3.9 16,4.1 10.238,6 15.7,7.3
  Top Layer region: 24,7.5 18.2,7.5 12.1,6 12.1,5.8 17.7,4 12.1,2.2 12.1,2 18.2,0.5 24,0.5 24,0.7 18.5,2 24.3,3.9 24.3,4.1 18.538,6 24,7.3
  Top Layer region: 28.5,7.5 26.5,7.5 20.4,6 20.4,5.8 26,4 20.4,2.2 20.4,2 26.5,0.5 28.5,0.5 28.5,2
  silkscreen extent 1.32,0.82 27.68,7.2
TP_1.0_SMD [mm] "Test Point, 1.0 mm, SMD (170509)"
  round 1 smd paste-0.501: 1(0,0)
  body extent -0.5,-0.5 0.5,0.5, height 0.04
U-DFN2018-6_M050_2.0X1.8_EP [mm] "U-DFN2018-6, 6-Lead, 2.0x1.8x0.58. Exposed Pad (Diodes Inc)"
  rrect5% 0.35x0.25 smd mask+0.04: 1(-0.975,0.5) 2(-0.975,0) 3(-0.975,-0.5) 4(0.975,-0.5) 5(0.975,0) 6(0.975,0.5)
  rrect5% 1.2x1.6 smd mask+0.04: 7(0,0)
  body extent -0.9,-1 0.9,1, height 0.62
VQFN24_M050_3.5X5.5_EP_TI_RHL [mm] "VQFN 24 Leads, Pitch 0.50 3.5x5.0x0.9, TI: RHL (171011)"
  rrect20% 0.28x0.99 smd: 1(-0.75,2.795) 12(-0.75,-2.795) 13(0.75,-2.795) 24(0.75,2.795)
  rrect20% 0.99x0.28 smd: 2(-1.795,2.25) 3(-1.795,1.75) 4(-1.795,1.25) 5(-1.795,0.75) 6(-1.795,0.25) 7(-1.795,-0.25) 8(-1.795,-0.75) 9(-1.795,-1.25) 10(-1.795,-1.75) 11(-1.795,-2.25) 14(1.795,-2.25) 15(1.795,-1.75) 16(1.795,-1.25) 17(1.795,-0.75) 18(1.795,-0.25) 19(1.795,0.25) 20(1.795,0.75) 21(1.795,1.25) 22(1.795,1.75) 23(1.795,2.25)
  rrect5% 2.05x4.05 smd: 25(0,0)
  Top Layer region: 0.39,-3.26 0.39,-2 -0.39,-2 -0.39,-3.26 -0.39,-3.266 -0.385,-3.277 -0.377,-3.285 -0.366,-3.29 -0.36,-3.29 -0.36,-3.29 -0.14,-3.29 -0.134,-3.29 -0.123,-3.285 -0.115,-3.277 -0.11,-3.266 -0.11,-3.26 -0.11,-3.26 -0.11,-2.32 -0.11,-2.316 -0.107,-2.309 -0.101,-2.303 -0.094,-2.3 -0.09,-2.3 -0.09,-2.3 0.09,-2.3 0.094,-2.3 0.101,-2.303 0.107,-2.309 0.11,-2.316 0.11,-2.32 0.11,-2.32 0.11,-3.26 0.11,-3.266 0.115,-3.277 0.123,-3.285 0.134,-3.29 0.14,-3.29 0.14,-3.29 0.36,-3.29 0.366,-3.29 0.377,-3.285 0.385,-3.277 0.39,-3.266 0.39,-3.26
  Top Layer region: -0.39,3.26 -0.39,2 0.39,2 0.39,3.26 0.39,3.266 0.385,3.277 0.377,3.285 0.366,3.29 0.36,3.29 0.36,3.29 0.14,3.29 0.134,3.29 0.123,3.285 0.115,3.277 0.11,3.266 0.11,3.26 0.11,3.26 0.11,2.32 0.11,2.316 0.107,2.309 0.101,2.303 0.094,2.3 0.09,2.3 0.09,2.3 -0.09,2.3 -0.094,2.3 -0.101,2.303 -0.107,2.309 -0.11,2.316 -0.11,2.32 -0.11,2.32 -0.11,3.26 -0.11,3.266 -0.115,3.277 -0.123,3.285 -0.134,3.29 -0.14,3.29 -0.14,3.29 -0.36,3.29 -0.366,3.29 -0.377,3.285 -0.385,3.277 -0.39,3.266 -0.39,3.26
  body extent -1.75,-2.75 1.75,2.75, height 1
VSSOP10_M050_W3.0_TI_DGS [mm] "VSSOP, 10-Leads, 3.0x3.0x(max1.1), Pitch 0.50mm, (TI: DGS) (190816)"
  rrect20% 1.45x0.3 smd: 1(-2.2,1) 2(-2.2,0.5) 3(-2.2,0) 4(-2.2,-0.5) 5(-2.2,-1) 6(2.2,-1) 7(2.2,-0.5) 8(2.2,0) 9(2.2,0.5) 10(2.2,1)
  body extent -1.5,-1.5 1.5,1.5, height 1.1
WCON_1125B-1210_HOR_PEG-2X10 [mm] "WCON 2x10 header (201021)"
  rrect50% 1.27x3.175 smd: 1(-1.27,4.24) 2(-1.27,8.43) 3(1.27,4.24) 4(1.27,8.43) 5(3.81,4.24) 6(3.81,8.43) 7(6.35,4.24) 8(6.35,8.43) 9(8.89,4.24) 10(8.89,8.43) 11(11.43,4.24) 12(11.43,8.43) 13(13.97,4.24) 14(13.97,8.43) 15(16.51,4.24) 16(16.51,8.43) 17(19.05,4.24) 18(19.05,8.43) 19(21.59,4.24) 20(21.59,8.43)
  round 0 hole 1.9 unplated paste+0.91 mask+0.1: M1(0,0) M2(20.32,0)
  body extent -2.54,-7.11 22.86,9.15, height 6.1
WCON_3132_HDR_M127_SMD-2X10 [mm] "WCON_3132_HDR_M127_SMD-2X10 (210215)"
  rrect50% 0.74x2.4 smd: 1(-5.715,-1.95) 2(-5.715,1.95) 3(-4.445,-1.95) 4(-4.445,1.95) 5(-3.175,-1.95) 6(-3.175,1.95) 7(-1.905,-1.95) 8(-1.905,1.95) 9(-0.635,-1.95) 10(-0.635,1.95) 11(0.635,-1.95) 12(0.635,1.95) 13(1.905,-1.95) 14(1.905,1.95) 15(3.175,-1.95) 16(3.175,1.95) 17(4.445,-1.95) 18(4.445,1.95) 19(5.715,-1.95) 20(5.715,1.95)
  body extent -6.35,-4.53 6.35,2.84, height 6.58
WSON8_M050_3.0X2.5_EP_TI_NGM [mm] "WSON8, Pitch 0.5, 3.0x2.5x0.8 EP TI: NGM (181205)"
  rrect20% 0.5x0.25 smd mask+0.051: 1(-1.15,0.75) 2(-1.15,0.25) 3(-1.15,-0.25) 4(-1.15,-0.75) 5(1.15,-0.75) 6(1.15,-0.25) 7(1.15,0.25) 8(1.15,0.75)
  rrect10% 1.2x1.5 smd mask+0.051: 9(0,0)
  body extent -1.5,-1.25 1.5,1.25, height 0.8
X2-DFN1006-2 [mm] "Diodes case X2-DFN1006-2 part DESD5V0S1BLD (201012)"
  rrect20% 0.4x0.7 smd mask+0.04: 1(-0.35,0) 2(0.35,0)
  body extent -0.5,-0.3 0.5,0.3, height 0.41
X2-DFN1010-6_M035_DIODES [mm] "X2-DFN1010-6 Pitch 0.35 1.0x1.0x0.4, Diodes Inc (181025)"
  rrect20% 0.55x0.2 smd mask+0.04: 1(-0.35,0.35) 2(-0.35,0) 3(-0.35,-0.35) 4(0.35,-0.35) 5(0.35,0) 6(0.35,0.35)
  body extent -0.5,-0.5 0.5,0.5, height 0.41
X2-DFN2015-3_DIODES [mm] "X2-DFN2015-3 DIODES (181204)"
  rrect10% 0.5x0.31 smd mask+0.07: 1(-0.9,0.5) 2(-0.9,-0.5)
  rrect10% 0.75x0.31 smd mask+0.07: 3(0.775,0)
  Top Layer region: 0.5,0.55 0.5,-0.55 0.5,-0.57 0.485,-0.607 0.457,-0.635 0.42,-0.65 0.4,-0.65 0.4,-0.65 -0.4,-0.65 -0.42,-0.65 -0.457,-0.635 -0.485,-0.607 -0.5,-0.57 -0.5,-0.55 -0.5,-0.55 -0.5,0.55 -0.5,0.57 -0.485,0.607 -0.457,0.635 -0.42,0.65 -0.4,0.65 -0.4,0.65 0.4,0.65 0.42,0.65 0.457,0.635 0.485,0.607 0.5,0.57 0.5,0.55
  body extent -1.04,-0.79 1.04,0.79, height 0.4
X_KDS_DSX211SH_2.0X1.65-4 [mm] "X_KDS_DSX211SH_2.0X1.65-4 (190312)"
  rrect20% 0.9x0.8 smd: 1(-0.7,-0.55) 2(0.7,-0.55) 3(0.7,0.55) 4(-0.7,0.55)
  body extent -1.07,-0.87 1.07,0.87, height 0.5
X_TAI-SAW-TZ2528C_2.05X1.2-2 [mm]
  rrect50% 0.7x1.4 smd: 1(-0.75,0) 2(0.75,0)
  body extent -1,-0.6 1,0.6, height 0.6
